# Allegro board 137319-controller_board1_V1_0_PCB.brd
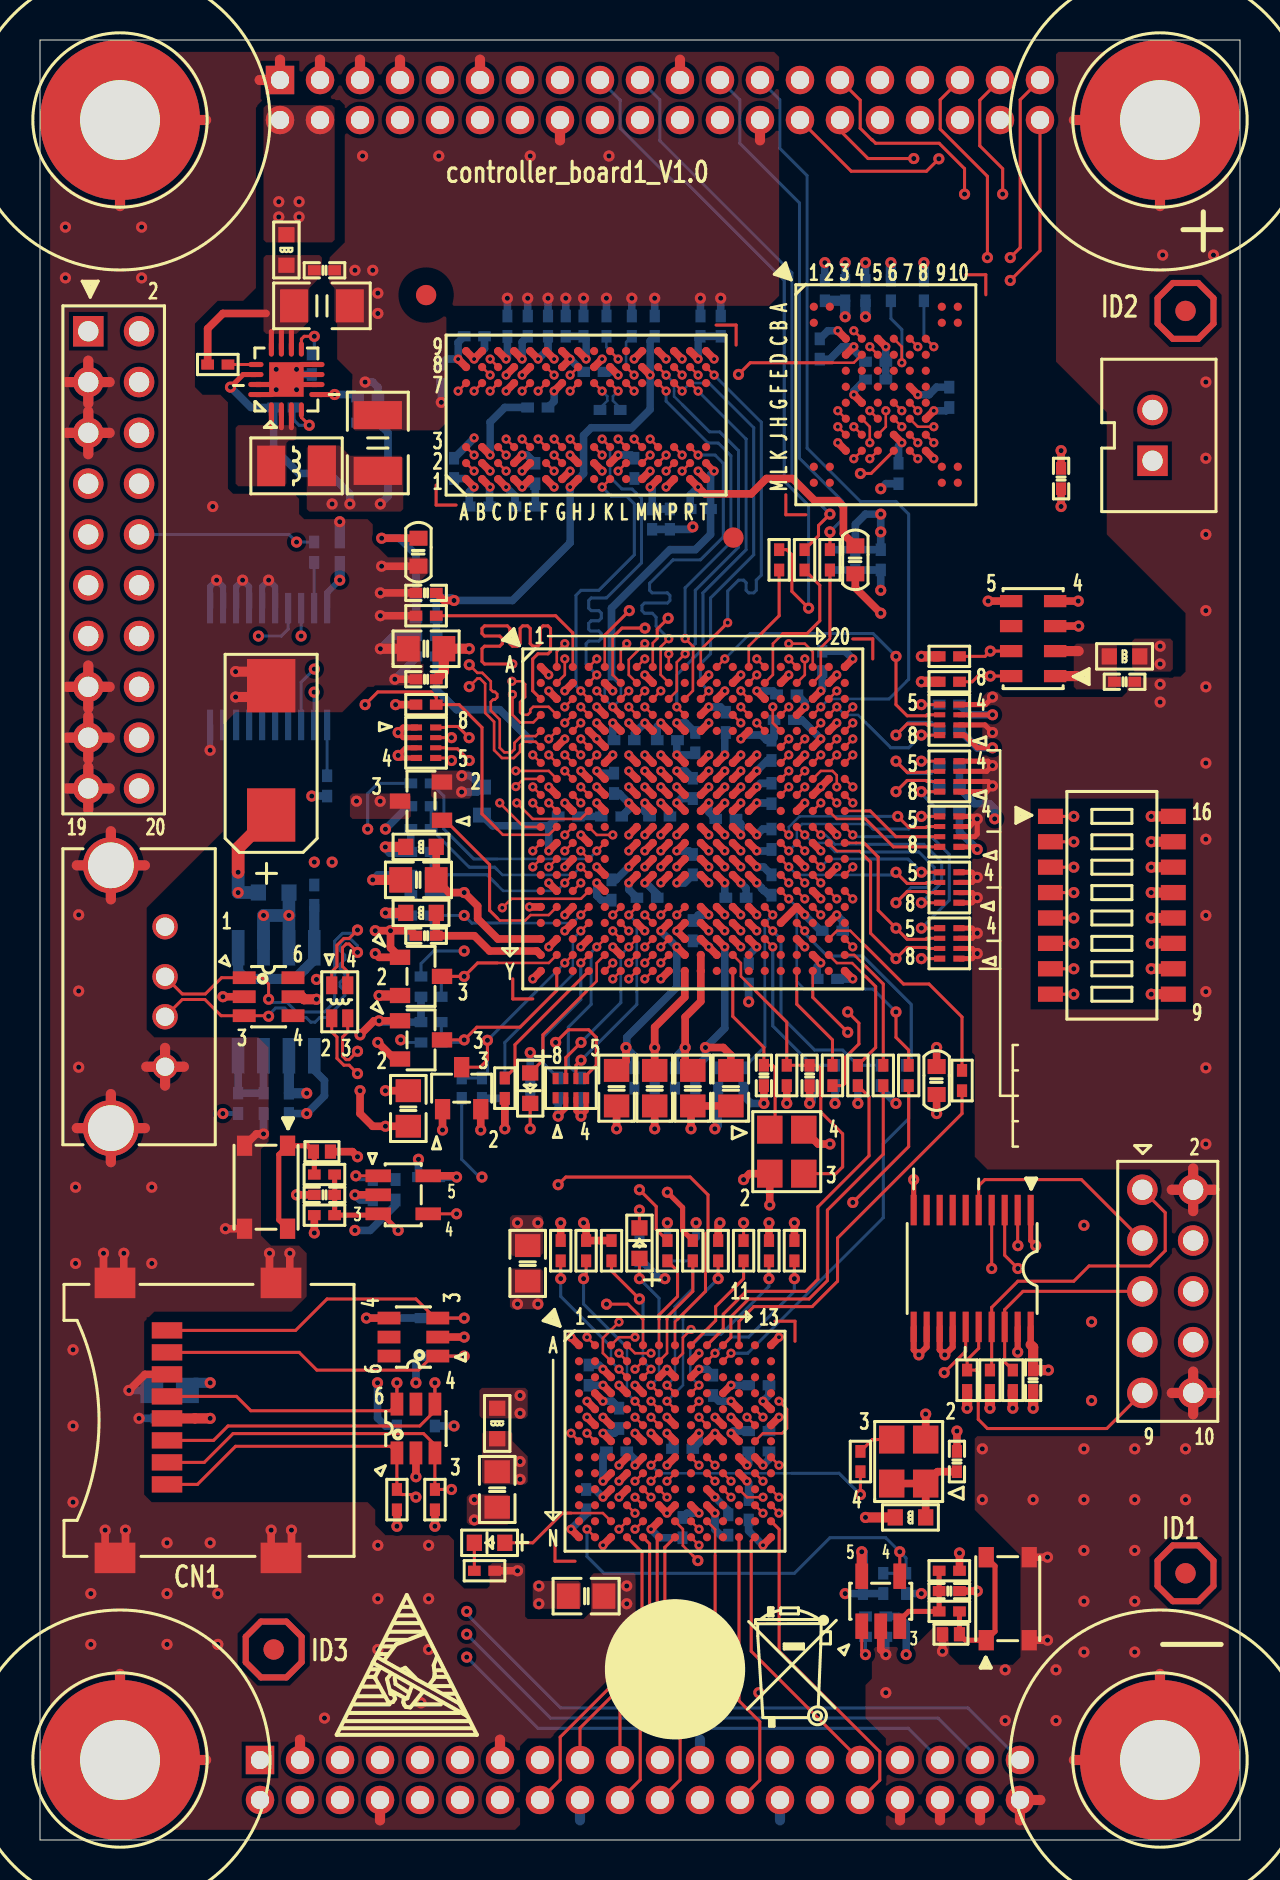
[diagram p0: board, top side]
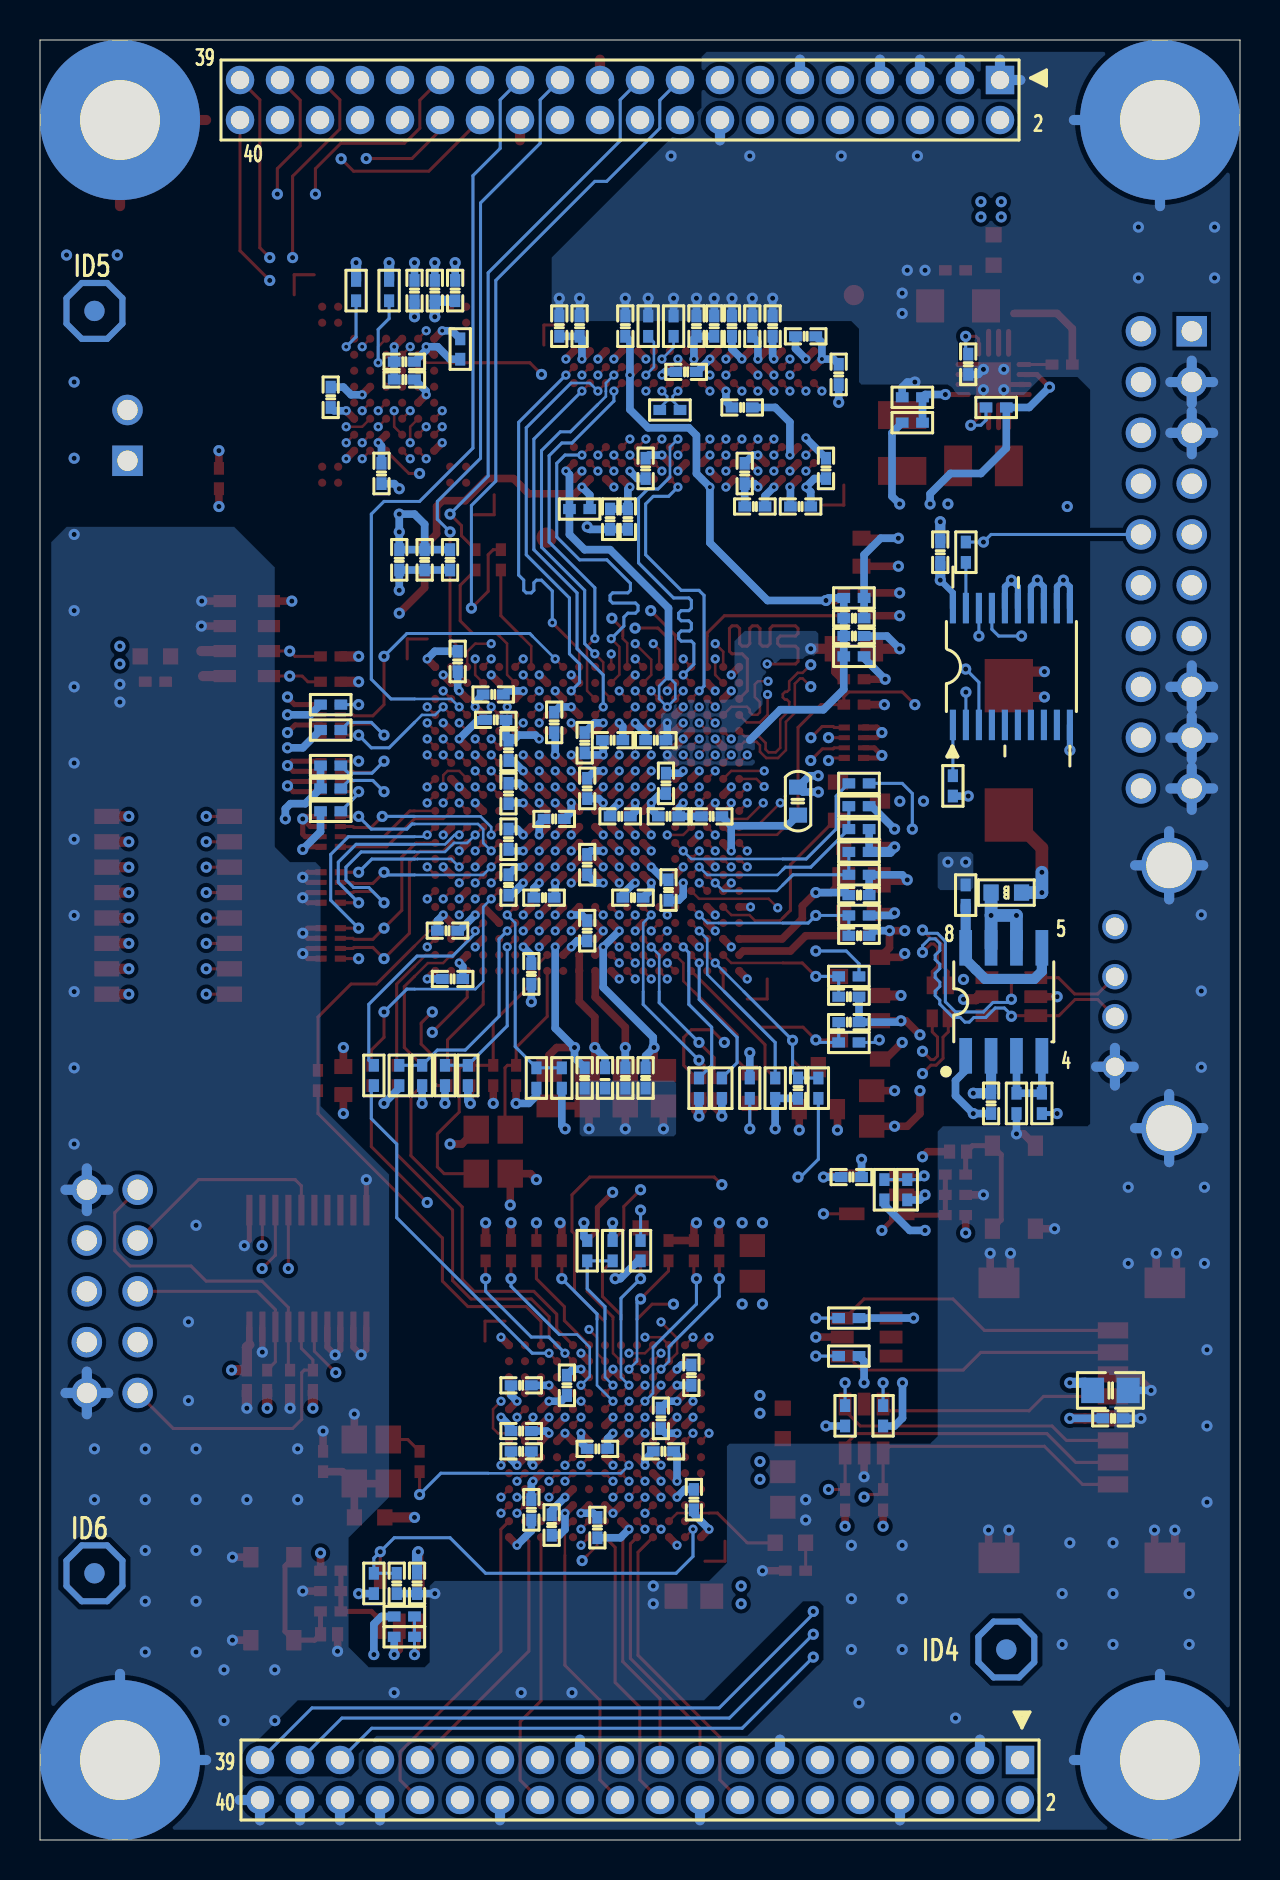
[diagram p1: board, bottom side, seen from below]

Outline 60 x 90 mm; copper layers: TOP, GND02, ART03, ART04, POWER05, BOTTOM. Coordinates in mm from the lower left corner of the outline.
Outline path: 0,90 0,0 60,0 60,90 0,90

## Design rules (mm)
net group DIFFPAIR0: nets USB_N USB_P
net group DIFFPAIR1: nets USB1_DN USB1_DP
net group DIFFPAIR2: nets USB0_DN USB0_DP

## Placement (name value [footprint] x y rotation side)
C1  0.1u  [C0402]  14.99 64.39 90 bottom
C2  0.1u  [C0402]  51.05 68.07 270 top
C3  0.1u  [C0402]  19.3 61.09 0 bottom
C4  0.1u  [C0402]  19.3 60.2 180 bottom
C5  0.1u  [C0402]  19.3 62.36 180 top
C6  0.1u  [C0402]  30.73 75.69 90 bottom
C7  1000p  [C0402]  23.37 75.69 90 bottom
C8  0.1u  [C0402]  21.97 66.67 0 bottom
C9  1000p  [C0402]  27.18 75.69 90 bottom
C10  0.1u  [C0402]  33.02 75.69 90 bottom
C11  1000p  [C0402]  26.29 75.69 90 bottom
C12  0.1u  [C0402]  34.04 75.69 90 bottom
C13  1000p  [C0402]  20.7 68.58 90 bottom
C14  0.1u  [C0402]  24.38 75.69 90 bottom
C15  1000p  [C0402]  24.26 66.67 0 bottom
C16  0.1u  [C0402]  21.72 75.18 0 bottom
C17  1000p  [C0402]  24.77 68.33 270 bottom
C18  0.1u  [C0402]  25.4 75.69 90 bottom
C19  1000p  [C0402]  30.61 66.04 270 bottom
C20  0.1u  [C0402]  27.69 73.41 180 bottom
C21  1000p  [C0402]  31.5 66.04 270 bottom
C22  0.1u  [C0402]  24.89 71.63 180 bottom
C23  1000p  [C0402]  20.07 73.28 270 bottom
C24  0.1u  [C0402]  29.72 68.58 270 bottom
C25  0.1u  [C0402]  41.78 73.91 0 bottom
C26  0.1u  [C0402]  42.93 68.33 270 bottom
C27  0.1u  [C0402]  45.47 72.14 90 bottom
C28  0.1u  [C0402]  41.78 73.03 0 bottom
C29  0.1u  [C0402]  19.56 42.16 180 bottom
C30  12p  [C0402]  38.48 38.23 270 top
C31  12p  [C0402]  36.2 38.23 270 top
C32  0.1u  [C0402]  22.1 37.59 270 bottom
C33  0.1u  [C0402]  19.56 40.89 180 bottom
C34  0.1u  [C0402]  19.05 45.21 180 bottom
C35  0.1u  [C0402]  54.23 57.91 0 top
C36  0.1u  [C0402]  19.43 33.15 180 bottom
C37  0.1u  [C0402]  14.22 32.26 180 top
C38  4.7u  [C0603]  40.77 64.01 270 top
C39  0.1u  [C0402]  28.57 51.18 0 bottom
C40  0.1u  [C0402]  28.7 52.83 270 bottom
C41  0.1u  [C0402]  34.29 55.88 270 bottom
C42  0.1u  [C0402]  26.42 51.18 180 bottom
C43  0.1u  [C0402]  31.37 54.99 0 bottom
C44  0.1u  [C0402]  29.21 54.99 0 bottom
C45  0.1u  [C0402]  19.3 58.04 180 top
C46  0.1u  [C0402]  32.64 45.47 270 bottom
C47  10u  [C0805]  19.3 59.56 180 top
C48  4.7u  [C0603]  22.1 51.94 270 bottom
C49  0.1u  [C0402]  36.58 47.75 90 bottom
C50  0.1u  [C0402]  34.29 51.05 180 bottom
C51  0.1u  [C0402]  36.58 50.04 90 bottom
C52  0.1u  [C0402]  36.58 52.32 90 bottom
C53  0.1u  [C0402]  28.57 47.5 270 bottom
C54  0.1u  [C0402]  36.58 54.48 90 bottom
C55  0.1u  [C0402]  34.8 47.12 0 bottom
C56  0.1u  [C0402]  32.64 52.58 270 bottom
C57  0.1u  [C0402]  30.99 51.18 0 bottom
C58  0.1u  [C0402]  32.64 48.77 90 bottom
C59  0.1u  [C0402]  32.77 54.86 270 bottom
C60  0.1u  [C0402]  30.35 47.12 180 bottom
C61  10u  [C0805]  34.54 37.59 270 top
C62  0.1u  [C0402]  32.77 38.1 270 bottom
C63  10u  [C0805]  18.41 36.58 270 top
C64  0.1u  [C0402]  39.37 43.05 0 bottom
C65  0.1u  [C0402]  40.77 64.01 90 bottom
C66  0.1u  [C0402]  39.12 58.93 90 bottom
C67  0.1u  [C0402]  35.43 43.31 270 bottom
C68  0.1u  [C0402]  39.62 45.47 0 bottom
C69  0.1u  [C0402]  39.5 64.01 90 bottom
C70  0.1u  [C0402]  40.26 77.47 90 bottom
C71  0.1u  [C0402]  37.21 56.01 180 bottom
C72  0.1u  [C0402]  37.34 57.28 0 bottom
C73  0.1u  [C0402]  41.27 77.47 90 bottom
C74  0.1u  [C0402]  39.24 77.47 90 bottom
C75  4.7u  [C0603]  44.83 37.97 270 top
C76  0.1u  [C0402]  42.04 64.01 90 bottom
C77  0.1u  [C0402]  31.75 38.1 270 bottom
C78  10u  [C0805]  32.64 37.59 270 top
C79  4.7u  [C0603]  18.92 64.39 270 top
C80  0.1u  [C0402]  29.72 38.1 270 bottom
C81  10u  [C0805]  28.83 37.59 270 top
C82  0.1u  [C0402]  30.73 38.1 270 bottom
C83  10u  [C0805]  30.73 37.59 270 top
C84  0.1u  [C0402]  19.3 45.21 180 top
C85  0.1u  [C0402]  19.05 47.24 180 bottom
C86  10u  [C0805]  18.92 48.01 180 top
C87  10u  [C0805]  6.48 22.48 180 bottom
C88  0.1u  [C0402]  6.35 21.08 0 bottom
C89  220u  [TC7343]  11.56 54.48 90 top
C90  0.1u  [C0402]  12.45 36.83 270 bottom
C91  0.1u  [C0402]  45.85 18.92 90 top
C92  0.1u  [C0402]  42.16 12.83 270 bottom
C93  0.1u  [C0402]  41.15 12.83 270 bottom
C94  0.1u  [C0402]  45.47 12.45 0 top
C95  10u  [C0805]  27.3 12.19 0 top
C96  1u  [C0402]  28.96 21.08 90 bottom
C97  0.1u  [C0402]  35.94 20.45 0 bottom
C98  0.1u  [C0402]  27.3 17.02 270 bottom
C99  0.1u  [C0402]  32.13 19.56 180 bottom
C100  0.1u  [C0402]  28.83 19.43 0 bottom
C101  10u  [C0805]  22.86 17.53 270 top
C102  1u  [C0402]  35.94 22.73 0 bottom
C103  0.1u  [C0402]  27.43 23.24 90 bottom
C104  0.1u  [C0402]  34.42 15.75 270 bottom
C105  10u  [C0805]  24.38 28.83 270 top
C106  1u  [C0402]  33.66 22.73 270 bottom
C107  0.1u  [C0402]  35.43 16.51 270 bottom
C108  0.1u  [C0402]  32.13 15.62 270 bottom
C109  0.1u  [C0402]  35.94 19.43 0 bottom
C110  0.1u  [C0402]  49.66 22.99 270 top
C111  22u  [C1210]  16.89 69.85 90 top
C112  47u  [C1206]  14.1 76.71 0 top
C113  0.1u  [C0402]  14.22 78.49 0 top
C114  160p  [C0402]  13.59 73.79 270 bottom
CN1  47219-2001  [SD12-47219-2001]  6.35 17.78 270 top
D1  APT1608SYCK  [D0603]  24.51 37.59 270 top
D2  BAT54S  [SOT23-3-095-3X1_4]  21.08 37.59 0 top
D3  BAT54S  [SOT23-3-095-3X1_4]  19.05 43.18 270 top
D4  BAT54S  [SOT23-3-095-3X1_4]  19.05 40.01 270 top
D5  Rclamp0531t  [SLP1006P2T]  14.1 34.42 180 top
D6  APT1608SYCK  [D0603]  22.48 14.86 180 top
D7  Rclamp0531t  [SLP1006P2T]  45.55 10.29 0 top
D8  APT1608SYCK  [D0603]  29.97 29.84 90 top
FB1  BLM18PG121SH1D  [FB0603]  54.23 59.18 0 top
FB2  BLM18PG121SH1D  [FB0603]  19.05 49.66 180 top
FB3  BLM18PG121SH1D  [FB0603]  19.05 46.35 180 top
FB4  BLM18PG121SH1D  [FB0603]  11.68 47.37 0 bottom
FB5  BLM18PG121SH1D  [FB0603]  43.52 16.13 180 top
FB6  BLM18PG121SH1D  [FB0603]  22.86 20.83 270 top
FB7  BLM18PG121SH1D  [FB0603]  12.32 79.5 270 top
H1  MH-7R4D3R2  [HOLE315-157]  4 4 0 top
H2  MH-7R4D3R2  [HOLE315-157]  56 4 0 top
H3  MH-7R4D3R2  [HOLE315-157]  56 86 0 top
H4  MH-7R4D3R2  [HOLE315-157]  4 86 0 top
J1  877584017  [HD40-2_0]  31 87 0 bottom
J2  877584017  [HD40-2_0]  30 3 0 bottom
J3  90131-1090  [HD20-2_54]  3.68 64.01 270 top
J4  0901311081  [SIP2-2_54]  55.63 70.23 270 top
J5  1734366-3  [USB4-AF]  4.95 42.16 270 top
J6  0901311085  [HD10-2_54]  56.39 27.43 270 top
L1  ACM2012H  [L4-0805]  14.99 41.91 270 top
L2  2.2uH  [L1008]  12.83 68.71 0 top
NOREF  -  []  281.94 115.57 0 top
NOREF#2  -  []  32.26 8.76 0 top
NOREF#3  -  []  459.86 195.16 0 top
NOREF#4  -  []  140.97 -11.43 0 top
NOREF#5  -  []  0 90 0 top
NOREF#6  -  []  459.86 210.4 0 top
NOREF#7  -  []  459.86 202.78 0 top
NOREF#8  -  []  40.13 8.76 0 top
NOREF#9  -  []  434.46 210.4 0 top
NOREF#10  -  [unnamed#2]  57.28 13.34 0 top
NOREF#11  -  []  257.81 180.34 0 top
NOREF#12  -  [unnamed#2]  11.68 9.53 0 top
NOREF#13  -  [unnamed#2]  57.28 76.45 0 top
NOREF#14  -  []  434.46 202.78 0 top
NOREF#15  -  []  434.46 195.16 0 top
NOREF#16  -  []  17.65 8.26 0 top
NOREF#17  -  []  250.32 7.75 0 top
NOREF#18  -  []  -19.05 -43.18 0 top
NOREF#19  -  []  250.32 63.75 0 top
NOREF#20  -  []  0 0 90 top
NOREF#21  -  [unnamed#2]  11.68 9.53 180 bottom
NOREF#22  -  [unnamed#2]  57.28 13.34 180 bottom
NOREF#23  -  [unnamed#2]  57.28 76.45 180 bottom
Q1  PBSS4021NT  [SOT23-3-095-3X1_4]  19.05 51.94 90 top
R1  0  [R0402]  45.47 56.77 0 bottom
R2  0  [R0402]  45.47 55.5 0 bottom
R3  0  [R0402]  45.47 53.72 0 bottom
R4  0  [R0402]  45.47 52.58 0 bottom
R5  0  [R0402]  45.47 51.44 0 bottom
R6  0  [R0402]  14.36 52.7 270 bottom
R7  0  [R0402]  13.71 64.39 90 bottom
R8  240  [R0402]  19.3 62.1 0 bottom
R9  240  [R0402]  19.3 59.18 180 bottom
R10  100  [R0402]  28.51 71.5 0 bottom
R11  10K  [R0402]  33.02 66.55 0 bottom
R12  240  [R0402]  19.3 61.21 180 top
R13  240  [R0402]  29.59 75.69 90 bottom
R14  10K  [R0402]  28.32 75.69 90 bottom
R15  4.7K  [R0402]  38.99 74.55 90 bottom
R16  4.7K  [R0402]  42.55 77.47 270 bottom
R17  4.7K  [R0402]  44.2 77.47 270 bottom
R18  33  [R0402]  42.16 38.23 270 top
R19  33  [R0402]  43.43 38.23 90 top
R20  33  [R0402]  39.62 38.23 270 top
R21  33  [R0402]  40.89 38.23 270 top
R22  33  [R0402]  46.1 37.97 270 top
R23  33  [R0402]  43.31 38.23 270 bottom
R24  33  [R0402]  39.5 64.01 270 top
R25  33  [R0402]  38.23 64.01 270 top
R26  33  [R0402]  36.96 64.01 270 top
R27  4.7K  [R0402]  19.3 56.77 180 top
R28  33  [R0402]  19.05 52.83 0 bottom
R29  4.7K  [R0402]  33.91 38.1 90 bottom
R30  4.7K  [R0402]  35.18 38.1 270 bottom
R31  4.7K  [R0402]  42.04 38.23 90 bottom
R32  4.7K  [R0402]  40.89 38.23 270 bottom
R33  4.7K  [R0402]  19.05 50.55 0 bottom
R34  4.7K  [R0402]  19.05 51.69 180 bottom
R35  4.7K  [R0402]  19.05 49.4 0 bottom
R36  4.7K  [R0402]  19.05 48.26 180 bottom
R37  1K  [R0402]  24.51 37.59 270 bottom
R38  1K  [R0402]  19.56 39.88 180 bottom
R39  1K  [R0402]  19.56 43.18 180 bottom
R40  1K  [R0402]  21.08 37.59 270 bottom
R42  2.2M  [R0402]  37.34 38.23 270 top
R46  10K  [R0402]  19.05 46.23 0 bottom
R47  10K  [R0402]  14.22 31.24 180 top
R48  10K  [R0402]  45.47 59.18 180 top
R49  10K  [R0402]  45.47 57.91 180 top
R50  10K  [R0402]  17.78 32.51 270 bottom
R51  0  [R0402]  14.22 33.27 180 top
R52  10K  [R0402]  16.64 32.51 270 bottom
R53  10K  [R0402]  17.85 17.02 90 top
R54  10K  [R0402]  19.75 17.02 90 top
R55  10K  [R0402]  19.75 21.21 90 bottom
R56  10K  [R0402]  17.85 21.21 90 bottom
R57  10K  [R0402]  19.56 24.2 0 bottom
R58  10K  [R0402]  19.56 26.1 0 bottom
R59  4.7K  [R0402]  38.61 38.23 270 bottom
R60  4.7K  [R0402]  39.75 38.23 270 bottom
R61  10K  [R0402]  13.72 47.24 90 bottom
R62  0  [R0402]  9.91 36.83 270 bottom
R63  4.7K  [R0402]  11.18 36.83 90 bottom
R64  33  [R0402]  35.18 29.46 270 top
R65  33  [R0402]  31.37 29.46 270 top
R66  0  [R0402]  32.64 29.46 270 top
R67  1K  [R0402]  22.23 13.46 0 top
R68  33  [R0402]  41.02 18.92 90 top
R69  10K  [R0402]  43.31 12.83 90 bottom
R70  10K  [R0402]  45.47 13.46 0 top
R71  10K  [R0402]  41.78 11.18 0 bottom
R72  0  [R0402]  45.47 11.43 0 top
R73  10K  [R0402]  41.78 10.16 0 bottom
R74  10K  [R0402]  32.64 29.46 270 bottom
R75  10K  [R0402]  31.37 29.46 90 bottom
R76  10K  [R0402]  37.72 29.46 270 top
R77  10K  [R0402]  36.45 29.46 270 top
R78  1K  [R0402]  29.97 29.46 90 bottom
R79  10K  [R0402]  26.04 29.46 270 top
R80  10K  [R0402]  28.57 29.46 270 top
R81  10K  [R0402]  33.91 29.46 270 top
R82  10K  [R0402]  27.3 29.46 270 top
R83  1K  [R0402]  47.5 22.99 90 top
R84  10K  [R0402]  48.64 22.99 90 top
R85  10K  [R0402]  46.35 22.99 90 top
R86  0  [R0402]  8.89 73.78 0 top
R87  4.7K  [R0402]  12.19 71.63 180 bottom
R88  130k  [R0402]  16.38 70.87 180 bottom
R89  150k  [R0402]  16.38 72.14 0 bottom
R90  1K  [R0402]  23.24 37.59 270 top
R91  1K  [R0402]  23.24 37.59 270 bottom
R92  1K  [R0402]  25.91 37.59 270 bottom
R93  1K  [R0402]  27.05 37.59 270 bottom
RA1  10k  [RN8-0402]  45.47 47.62 90 top
RA2  10k  [RN8-0402]  45.47 44.83 90 top
RA3  10k  [RN8-0402]  45.47 50.42 90 top
RA4  10k  [RN8-0402]  45.47 56.01 90 top
RA5  10k  [RN8-0402]  45.47 53.18 90 top
RA6  10k  [RN8-0402]  26.54 37.59 0 top
RA7  10k  [RN8-0402]  19.3 54.86 270 top
S1  97C08SRT  [SW16-1_27MM-4_55]  53.59 46.74 270 top
SW1  PTS810 SJM 250 SMTR LFS  [SW4-0403]  11.3 32.64 270 top
SW2  PTS810 SJM 250 SMTR LFS  [SW4-0403]  48.39 12.06 90 top
U2  MVF61NS151CMK50  [BGA364_0P8_17X17]  32.64 51.05 270 top
U3  MT41J64M16JT-15E IT  [BGA96-0_8-1609]  27.3 71.25 0 top
U4  MT29F2G08ABAEAH4-IT  [BGA63-0_8-1210]  42.29 72.26 270 top
U5  MS560702BA03-50  [DFN8-1_25-5_0X3_0-H1_0]  49.66 60.07 90 top
U7  RCLAMP0504S.TCT  [SOT23-6-095-2_9X1_6]  18.8 20.57 0 top
U8  RCLAMP0504S.TCT  [SOT23-6-095-2_9X1_6]  18.67 25.15 90 top
U9  TPS2042BDR  [SOP8-50-157]  11.81 41.91 180 bottom
U10  RCLAMP0504S.TCT  [SOT23-6-095-2_9X1_6]  11.43 42.16 270 top
U11  10M08SCU169I7G  [BGA169-0_8-1111]  31.75 19.94 270 top
U14  TPS62140ARGTR  [QFN16-050-0303LH]  12.32 73.03 0 top
U15  SN74LVCR2245APWR  [SOP20-26-173]  11.43 58.67 180 bottom
U16  SN74LVCR2245APWR  [SOP20-26-173]  46.61 28.57 180 top
U17  TPS3838K  [SOT23-5-095-2_9X1_6]  42.04 11.94 0 top
U18  TPS3838K  [SOT23-5-095-2_9X1_6]  18.16 32.26 270 top
X1  8MHz  [X4-3225]  43.43 18.92 90 top
Y1  24MHz  [X4-3225]  37.34 34.42 270 top

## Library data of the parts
C1-C88 C90-C114 = CAP
C89 = CAP_POL
CN1 = MICRO_SD_CARD
D1 D6 D8 = LED
D2-D4 = DIODE_SCHOTTKY_2
D5 D7 = DIODE-BI
FB1-FB7 = FB
H1-H4 = HOLE
J1 J2 = HEADER 20X2
J3 = HEADER 10X2
J4 = JUMPER
J5 = USB-A
J6 = HEADER 5X2
L1 = INDUCTOR-COM
L2 = INDUCTOR
Q1 = TRANSISTOR_NPN
R1-R9 R11-R13 R15-R40 R42 R46-R93 = RES
R10 = RES: signal model: RES_R0402_DISCRETE_100_100
R14 = RES: signal model: RES_R0402_DISCRETE_10K_10K
RA1-RA7 = RP4
S1 = SWITCH-8
SW1 SW2 = SWITCH-PUSH
U2 = MVF61NS151CMK50
U3 = DDR3SDRAM16
U4 = NAND16-BGA63
U5 = MS560702BA03
U7 U8 U10 = TVS_ARRAY4_P
U9 = TPS2042
U11 = 10M08SCU169
U14 = TPS62140
U15 U16 = SN74LVCR2245
U17 U18 = TPS3838K
X1 = CLOCK
Y1 = CRYSTAL-4

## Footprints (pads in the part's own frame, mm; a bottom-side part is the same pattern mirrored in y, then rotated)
BGA63-0_8-1210
  round 0.406 smd: A1(-4.4,-3.6) A2(-4.4,-2.8) A9(-4.4,2.8) A10(-4.4,3.6) B1(-3.6,-3.6) B9(-3.6,2.8) B10(-3.6,3.6) C3(-2.8,-2) C4(-2.8,-1.2) C5(-2.8,-0.4) C6(-2.8,0.4) C7(-2.8,1.2) C8(-2.8,2) D3(-2,-2) D4(-2,-1.2) D5(-2,-0.4) D6(-2,0.4) D7(-2,1.2) D8(-2,2) E3(-1.2,-2) E4(-1.2,-1.2) E5(-1.2,-0.4) E6(-1.2,0.4) E7(-1.2,1.2) E8(-1.2,2) F3(-0.4,-2) F4(-0.4,-1.2) F5(-0.4,-0.4) F6(-0.4,0.4) F7(-0.4,1.2) F8(-0.4,2) G3(0.4,-2) G4(0.4,-1.2) G5(0.4,-0.4) G6(0.4,0.4) G7(0.4,1.2) G8(0.4,2) H3(1.2,-2) H4(1.2,-1.2) H5(1.2,-0.4) H6(1.2,0.4) H7(1.2,1.2) H8(1.2,2) J3(2,-2) J4(2,-1.2) J5(2,-0.4) J6(2,0.4) J7(2,1.2) J8(2,2) K3(2.8,-2) K4(2.8,-1.2) K5(2.8,-0.4) K6(2.8,0.4) K7(2.8,1.2) K8(2.8,2) L1(3.6,-3.6) L2(3.6,-2.8) L9(3.6,2.8) L10(3.6,3.6) M1(4.4,-3.6) M2(4.4,-2.8) M9(4.4,2.8) M10(4.4,3.6)
BGA96-0_8-1609
  round 1.016 smd: (-8,6) (7.365,-6.127)
  round 0.406 smd: A1(-6,-3.2) A2(-6,-2.4) A3(-6,-1.6) A7(-6,1.6) A8(-6,2.4) A9(-6,3.2) B1(-5.2,-3.2) B2(-5.2,-2.4) B3(-5.2,-1.6) B7(-5.2,1.6) B8(-5.2,2.4) B9(-5.2,3.2) C1(-4.4,-3.2) C2(-4.4,-2.4) C3(-4.4,-1.6) C7(-4.4,1.6) C8(-4.4,2.4) C9(-4.4,3.2) D1(-3.6,-3.2) D2(-3.6,-2.4) D3(-3.6,-1.6) D7(-3.6,1.6) D8(-3.6,2.4) D9(-3.6,3.2) E1(-2.8,-3.2) E2(-2.8,-2.4) E3(-2.8,-1.6) E7(-2.8,1.6) E8(-2.8,2.4) E9(-2.8,3.2) F1(-2,-3.2) F2(-2,-2.4) F3(-2,-1.6) F7(-2,1.6) F8(-2,2.4) F9(-2,3.2) G1(-1.2,-3.2) G2(-1.2,-2.4) G3(-1.2,-1.6) G7(-1.2,1.6) G8(-1.2,2.4) G9(-1.2,3.2) H1(-0.4,-3.2) H2(-0.4,-2.4) H3(-0.4,-1.6) H7(-0.4,1.6) H8(-0.4,2.4) H9(-0.4,3.2) J1(0.4,-3.2) J2(0.4,-2.4) J3(0.4,-1.6) J7(0.4,1.6) J8(0.4,2.4) J9(0.4,3.2) K1(1.2,-3.2) K2(1.2,-2.4) K3(1.2,-1.6) K7(1.2,1.6) K8(1.2,2.4) K9(1.2,3.2) L1(2,-3.2) L2(2,-2.4) L3(2,-1.6) L7(2,1.6) L8(2,2.4) L9(2,3.2) M1(2.8,-3.2) M2(2.8,-2.4) M3(2.8,-1.6) M7(2.8,1.6) M8(2.8,2.4) M9(2.8,3.2) N1(3.6,-3.2) N2(3.6,-2.4) N3(3.6,-1.6) N7(3.6,1.6) N8(3.6,2.4) N9(3.6,3.2) P1(4.4,-3.2) P2(4.4,-2.4) P3(4.4,-1.6) P7(4.4,1.6) P8(4.4,2.4) P9(4.4,3.2) R1(5.2,-3.2) R2(5.2,-2.4) R3(5.2,-1.6) R7(5.2,1.6) R8(5.2,2.4) R9(5.2,3.2) T1(6,-3.2) T2(6,-2.4) T3(6,-1.6) T7(6,1.6) T8(6,2.4) T9(6,3.2)
BGA169-0_8-1111
  round 0.406 smd: A1(-4.8,-4.8) A2(-4.8,-4) A3(-4.8,-3.2) A4(-4.8,-2.4) A5(-4.8,-1.6) A6(-4.8,-0.8) A7(-4.8,0) A8(-4.8,0.8) A9(-4.8,1.6) A10(-4.8,2.4) A11(-4.8,3.2) A12(-4.8,4) A13(-4.8,4.8) B1(-4,-4.8) B2(-4,-4) B3(-4,-3.2) B4(-4,-2.4) B5(-4,-1.6) B6(-4,-0.8) B7(-4,0) B8(-4,0.8) B9(-4,1.6) B10(-4,2.4) B11(-4,3.2) B12(-4,4) B13(-4,4.8) C1(-3.2,-4.8) C2(-3.2,-4) C3(-3.2,-3.2) C4(-3.2,-2.4) C5(-3.2,-1.6) C6(-3.2,-0.8) C7(-3.2,0) C8(-3.2,0.8) C9(-3.2,1.6) C10(-3.2,2.4) C11(-3.2,3.2) C12(-3.2,4) C13(-3.2,4.8) D1(-2.4,-4.8) D2(-2.4,-4) D3(-2.4,-3.2) D4(-2.4,-2.4) D5(-2.4,-1.6) D6(-2.4,-0.8) D7(-2.4,0) D8(-2.4,0.8) D9(-2.4,1.6) D10(-2.4,2.4) D11(-2.4,3.2) D12(-2.4,4) D13(-2.4,4.8) E1(-1.6,-4.8) E2(-1.6,-4) E3(-1.6,-3.2) E4(-1.6,-2.4) E5(-1.6,-1.6) E6(-1.6,-0.8) E7(-1.6,0) E8(-1.6,0.8) E9(-1.6,1.6) E10(-1.6,2.4) E11(-1.6,3.2) E12(-1.6,4) E13(-1.6,4.8) F1(-0.8,-4.8) F2(-0.8,-4) F3(-0.8,-3.2) F4(-0.8,-2.4) F5(-0.8,-1.6) F6(-0.8,-0.8) F7(-0.8,0) F8(-0.8,0.8) F9(-0.8,1.6) F10(-0.8,2.4) F11(-0.8,3.2) F12(-0.8,4) F13(-0.8,4.8) G1(0,-4.8) G2(0,-4) G3(0,-3.2) G4(0,-2.4) G5(0,-1.6) G6(0,-0.8) G7(0,0) G8(0,0.8) G9(0,1.6) G10(0,2.4) G11(0,3.2) G12(0,4) G13(0,4.8) H1(0.8,-4.8) H2(0.8,-4) H3(0.8,-3.2) H4(0.8,-2.4) H5(0.8,-1.6) H6(0.8,-0.8) H7(0.8,0) H8(0.8,0.8) H9(0.8,1.6) H10(0.8,2.4) H11(0.8,3.2) H12(0.8,4) H13(0.8,4.8) J1(1.6,-4.8) J2(1.6,-4) J3(1.6,-3.2) J4(1.6,-2.4) J5(1.6,-1.6) J6(1.6,-0.8) J7(1.6,0) J8(1.6,0.8) J9(1.6,1.6) J10(1.6,2.4) J11(1.6,3.2) J12(1.6,4) J13(1.6,4.8) K1(2.4,-4.8) K2(2.4,-4) K3(2.4,-3.2) K4(2.4,-2.4) K5(2.4,-1.6) K6(2.4,-0.8) K7(2.4,0) K8(2.4,0.8) K9(2.4,1.6) K10(2.4,2.4) K11(2.4,3.2) K12(2.4,4) K13(2.4,4.8) L1(3.2,-4.8) L2(3.2,-4) L3(3.2,-3.2) L4(3.2,-2.4) L5(3.2,-1.6) L6(3.2,-0.8) L7(3.2,0) L8(3.2,0.8) L9(3.2,1.6) L10(3.2,2.4) L11(3.2,3.2) L12(3.2,4) L13(3.2,4.8) M1(4,-4.8) M2(4,-4) M3(4,-3.2) M4(4,-2.4) M5(4,-1.6) M6(4,-0.8) M7(4,0) M8(4,0.8) M9(4,1.6) M10(4,2.4) M11(4,3.2) M12(4,4) M13(4,4.8) N1(4.8,-4.8) N2(4.8,-4) N3(4.8,-3.2) N4(4.8,-2.4) N5(4.8,-1.6) N6(4.8,-0.8) N7(4.8,0) N8(4.8,0.8) N9(4.8,1.6) N10(4.8,2.4) N11(4.8,3.2) N12(4.8,4) N13(4.8,4.8)
BGA364_0P8_17X17
  round 0.406 smd: A1(-7.6,-7.6) A2(-7.6,-6.8) A3(-7.6,-6) A4(-7.6,-5.2) A5(-7.6,-4.4) A6(-7.6,-3.6) A7(-7.6,-2.8) A8(-7.6,-2) A9(-7.6,-1.2) A10(-7.6,-0.4) A11(-7.6,0.4) A12(-7.6,1.2) A13(-7.6,2) A14(-7.6,2.8) A15(-7.6,3.6) A16(-7.6,4.4) A17(-7.6,5.2) A18(-7.6,6) A19(-7.6,6.8) A20(-7.6,7.6) B1(-6.8,-7.6) B2(-6.8,-6.8) B3(-6.8,-6) B4(-6.8,-5.2) B5(-6.8,-4.4) B6(-6.8,-3.6) B7(-6.8,-2.8) B8(-6.8,-2) B9(-6.8,-1.2) B10(-6.8,-0.4) B11(-6.8,0.4) B12(-6.8,1.2) B13(-6.8,2) B14(-6.8,2.8) B15(-6.8,3.6) B16(-6.8,4.4) B17(-6.8,5.2) B18(-6.8,6) B19(-6.8,6.8) B20(-6.8,7.6) C1(-6,-7.6) C2(-6,-6.8) C3(-6,-6) C4(-6,-5.2) C5(-6,-4.4) C6(-6,-3.6) C7(-6,-2.8) C8(-6,-2) C9(-6,-1.2) C10(-6,-0.4) C11(-6,0.4) C12(-6,1.2) C13(-6,2) C14(-6,2.8) C15(-6,3.6) C16(-6,4.4) C17(-6,5.2) C18(-6,6) C19(-6,6.8) C20(-6,7.6) D1(-5.2,-7.6) D2(-5.2,-6.8) D3(-5.2,-6) D4(-5.2,-5.2) D5(-5.2,-4.4) D6(-5.2,-3.6) D7(-5.2,-2.8) D8(-5.2,-2) D9(-5.2,-1.2) D10(-5.2,-0.4) D11(-5.2,0.4) D12(-5.2,1.2) D13(-5.2,2) D14(-5.2,2.8) D15(-5.2,3.6) D16(-5.2,4.4) D17(-5.2,5.2) D18(-5.2,6) D19(-5.2,6.8) D20(-5.2,7.6) E1(-4.4,-7.6) E2(-4.4,-6.8) E3(-4.4,-6) E4(-4.4,-5.2) E5(-4.4,-4.4) E6(-4.4,-3.6) E7(-4.4,-2.8) E8(-4.4,-2) E9(-4.4,-1.2) E10(-4.4,-0.4) E11(-4.4,0.4) E12(-4.4,1.2) E13(-4.4,2) E14(-4.4,2.8) E15(-4.4,3.6) E16(-4.4,4.4) E17(-4.4,5.2) E18(-4.4,6) E19(-4.4,6.8) E20(-4.4,7.6) F1(-3.6,-7.6) F2(-3.6,-6.8) F3(-3.6,-6) F4(-3.6,-5.2) F5(-3.6,-4.4) F16(-3.6,4.4) F17(-3.6,5.2) F18(-3.6,6) F19(-3.6,6.8) F20(-3.6,7.6) G1(-2.8,-7.6) G2(-2.8,-6.8) G3(-2.8,-6) G4(-2.8,-5.2) G5(-2.8,-4.4) G7(-2.8,-2.8) G8(-2.8,-2) G9(-2.8,-1.2) G10(-2.8,-0.4) G11(-2.8,0.4) G12(-2.8,1.2) G13(-2.8,2) G14(-2.8,2.8) G16(-2.8,4.4) G17(-2.8,5.2) G18(-2.8,6) G19(-2.8,6.8) G20(-2.8,7.6) H1(-2,-7.6) H2(-2,-6.8) H3(-2,-6) H4(-2,-5.2) H5(-2,-4.4) H7(-2,-2.8) H8(-2,-2) H9(-2,-1.2) H10(-2,-0.4) H11(-2,0.4) H12(-2,1.2) H13(-2,2) H14(-2,2.8) H16(-2,4.4) H17(-2,5.2) H18(-2,6) H19(-2,6.8) H20(-2,7.6) J1(-1.2,-7.6) J2(-1.2,-6.8) J3(-1.2,-6) J4(-1.2,-5.2) J5(-1.2,-4.4) J7(-1.2,-2.8) J8(-1.2,-2) J9(-1.2,-1.2) J10(-1.2,-0.4) J11(-1.2,0.4) J12(-1.2,1.2) J13(-1.2,2) J14(-1.2,2.8) J16(-1.2,4.4) J17(-1.2,5.2) J18(-1.2,6) J19(-1.2,6.8) J20(-1.2,7.6) K1(-0.4,-7.6) K2(-0.4,-6.8) K3(-0.4,-6) K4(-0.4,-5.2) K5(-0.4,-4.4) K7(-0.4,-2.8) K8(-0.4,-2) K9(-0.4,-1.2) K10(-0.4,-0.4) K11(-0.4,0.4) K12(-0.4,1.2) K13(-0.4,2) K14(-0.4,2.8) K16(-0.4,4.4) K17(-0.4,5.2) K18(-0.4,6) K19(-0.4,6.8) K20(-0.4,7.6) L1(0.4,-7.6) L2(0.4,-6.8) L3(0.4,-6) L4(0.4,-5.2) L5(0.4,-4.4) L7(0.4,-2.8) L8(0.4,-2) L9(0.4,-1.2) L10(0.4,-0.4) L11(0.4,0.4) L12(0.4,1.2) L13(0.4,2) L14(0.4,2.8) L16(0.4,4.4) L17(0.4,5.2) L18(0.4,6) L19(0.4,6.8) L20(0.4,7.6) M1(1.2,-7.6) M2(1.2,-6.8) M3(1.2,-6) M4(1.2,-5.2) M5(1.2,-4.4) M7(1.2,-2.8) M8(1.2,-2) M9(1.2,-1.2) M10(1.2,-0.4) M11(1.2,0.4) M12(1.2,1.2) M13(1.2,2) M14(1.2,2.8) M16(1.2,4.4) M17(1.2,5.2) M18(1.2,6) M19(1.2,6.8) M20(1.2,7.6) N1(2,-7.6) N2(2,-6.8) N3(2,-6) N4(2,-5.2) N5(2,-4.4) N7(2,-2.8) N8(2,-2) N9(2,-1.2) N10(2,-0.4) N11(2,0.4) N12(2,1.2) N13(2,2) N14(2,2.8) N16(2,4.4) N17(2,5.2) N18(2,6) N19(2,6.8) N20(2,7.6) P1(2.8,-7.6) P2(2.8,-6.8) P3(2.8,-6) P4(2.8,-5.2) P5(2.8,-4.4) P7(2.8,-2.8) P8(2.8,-2) P9(2.8,-1.2) P10(2.8,-0.4) P11(2.8,0.4) P12(2.8,1.2) P13(2.8,2) P14(2.8,2.8) P16(2.8,4.4) P17(2.8,5.2) P18(2.8,6) P19(2.8,6.8) P20(2.8,7.6) R1(3.6,-7.6) R2(3.6,-6.8) R3(3.6,-6) R4(3.6,-5.2) R5(3.6,-4.4) R16(3.6,4.4) R17(3.6,5.2) R18(3.6,6) R19(3.6,6.8) R20(3.6,7.6) T1(4.4,-7.6) T2(4.4,-6.8) T3(4.4,-6) T4(4.4,-5.2) T5(4.4,-4.4) T6(4.4,-3.6) T7(4.4,-2.8) T8(4.4,-2) T9(4.4,-1.2) T10(4.4,-0.4) T11(4.4,0.4) T12(4.4,1.2) T13(4.4,2) T14(4.4,2.8) T15(4.4,3.6) T16(4.4,4.4) T17(4.4,5.2) T18(4.4,6) T19(4.4,6.8) T20(4.4,7.6) U1(5.2,-7.6) U2(5.2,-6.8) U3(5.2,-6) U4(5.2,-5.2) U5(5.2,-4.4) U6(5.2,-3.6) U7(5.2,-2.8) U8(5.2,-2) U9(5.2,-1.2) U10(5.2,-0.4) U11(5.2,0.4) U12(5.2,1.2) U13(5.2,2) U14(5.2,2.8) U15(5.2,3.6) U16(5.2,4.4) U17(5.2,5.2) U18(5.2,6) U19(5.2,6.8) U20(5.2,7.6) V1(6,-7.6) V2(6,-6.8) V3(6,-6) V4(6,-5.2) V5(6,-4.4) V6(6,-3.6) V7(6,-2.8) V8(6,-2) V9(6,-1.2) V10(6,-0.4) V11(6,0.4) V12(6,1.2) V13(6,2) V14(6,2.8) V15(6,3.6) V16(6,4.4) V17(6,5.2) V18(6,6) V19(6,6.8) V20(6,7.6) W1(6.8,-7.6) W2(6.8,-6.8) W3(6.8,-6) W4(6.8,-5.2) W5(6.8,-4.4) W6(6.8,-3.6) W7(6.8,-2.8) W8(6.8,-2) W9(6.8,-1.2) W10(6.8,-0.4) W11(6.8,0.4) W12(6.8,1.2) W13(6.8,2) W14(6.8,2.8) W15(6.8,3.6) W16(6.8,4.4) W17(6.8,5.2) W18(6.8,6) W19(6.8,6.8) W20(6.8,7.6) Y1(7.6,-7.6) Y2(7.6,-6.8) Y3(7.6,-6) Y4(7.6,-5.2) Y5(7.6,-4.4) Y6(7.6,-3.6) Y7(7.6,-2.8) Y8(7.6,-2) Y9(7.6,-1.2) Y10(7.6,-0.4) Y11(7.6,0.4) Y12(7.6,1.2) Y13(7.6,2) Y14(7.6,2.8) Y15(7.6,3.6) Y16(7.6,4.4) Y17(7.6,5.2) Y18(7.6,6) Y19(7.6,6.8) Y20(7.6,7.6)
C0402
  rect 0.635x0.508 smd: 1(-0.508,0) 2(0.508,0)
C0603
  rect 0.75x0.9 smd: 1(-0.7,0) 2(0.7,0)
C0805
  rect 1.143x1.27 smd: 1(-0.889,0) 2(0.889,0)
C1206
  rect 1.397x1.651 smd: 1(-1.397,0) 2(1.397,0)
C1210
  rect 1.397x2.413 smd: 1(-1.397,0) 2(1.397,0)
D0603
  rect 0.762x0.813 smd: 1(-0.762,0) 2(0.762,0)
DFN8-1_25-5_0X3_0-H1_0
  rect 0.61x1.118 smd: 1(-1.875,-1.1) 2(-0.625,-1.1) 3(0.625,-1.1) 4(1.875,-1.1) 5(1.875,1.1) 6(0.625,1.1) 7(-0.625,1.1) 8(-1.875,1.1)
FB0603
  rect 0.762x0.813 smd: 1(-0.762,0) 2(0.762,0)
HD10-2_54
  round 1.524 hole 1.016: 1(-5.08,-1.27) 2(-5.08,1.27) 3(-2.54,-1.27) 4(-2.54,1.27) 5(0,-1.27) 6(0,1.27) 7(2.54,-1.27) 8(2.54,1.27) 9(5.08,-1.27) 10(5.08,1.27)
HD20-2_54
  rect 1.524x1.524 hole 1.016: 1(-11.43,-1.27)
  round 1.524 hole 1.016: 2(-11.43,1.27) 3(-8.89,-1.27) 4(-8.89,1.27) 5(-6.35,-1.27) 6(-6.35,1.27) 7(-3.81,-1.27) 8(-3.81,1.27) 9(-1.27,-1.27) 10(-1.27,1.27) 11(1.27,-1.27) 12(1.27,1.27) 13(3.81,-1.27) 14(3.81,1.27) 15(6.35,-1.27) 16(6.35,1.27) 17(8.89,-1.27) 18(8.89,1.27) 19(11.43,-1.27) 20(11.43,1.27)
HD40-2_0
  rect 1.422x1.422 hole 0.914: 1(-19,-1)
  round 1.422 hole 0.914: 2(-19,1) 3(-17,-1) 4(-17,1) 5(-15,-1) 6(-15,1) 7(-13,-1) 8(-13,1) 9(-11,-1) 10(-11,1) 11(-9,-1) 12(-9,1) 13(-7,-1) 14(-7,1) 15(-5,-1) 16(-5,1) 17(-3,-1) 18(-3,1) 19(-1,-1) 20(-1,1) 21(1,-1) 22(1,1) 23(3,-1) 24(3,1) 25(5,-1) 26(5,1) 27(7,-1) 28(7,1) 29(9,-1) 30(9,1) 31(11,-1) 32(11,1) 33(13,-1) 34(13,1) 35(15,-1) 36(15,1) 37(17,-1) 38(17,1) 39(19,-1) 40(19,1)
HOLE315-157
  round 8.001 hole 3.988: 1(0,0)
L4-0805
  rect 0.889x0.559 smd: 1(-0.825,-0.4) 2(0.825,-0.4) 3(0.825,0.4) 4(-0.825,0.4)
L1008
  rect 1.397x2.032 smd: 1(-1.27,0) 2(1.27,0)
QFN16-050-0303LH
  oval 0.254x0.762 smd: 1(-0.75,-1.525) 2(-0.25,-1.525) 3(0.25,-1.525) 4(0.75,-1.525) 9(0.75,1.525) 10(0.25,1.525) 11(-0.25,1.525) 12(-0.75,1.525)
  oval 0.762x0.254 smd: 5(1.525,-0.75) 6(1.525,-0.25) 7(1.525,0.25) 8(1.525,0.75) 13(-1.525,0.75) 14(-1.525,0.25) 15(-1.525,-0.25) 16(-1.525,-0.75)
  rect 1.727x1.727 smd: 17(0,0)
R0402
  rect 0.635x0.508 smd: 1(-0.508,0) 2(0.508,0)
RN8-0402
  rect 0.305x0.559 smd: 1(-0.762,-0.483) 4(0.762,-0.483) 5(0.762,0.483) 8(-0.762,0.483)
  rect 0.254x0.559 smd: 2(-0.254,-0.483) 3(0.254,-0.483) 6(0.254,0.483) 7(-0.254,0.483)
SD12-47219-2001
  rect 0.813x1.524 smd: 1(0,0) 2(-1.1,0) 3(-2.2,0) 4(-3.3,0) 5(-4.4,0) 6(-5.5,0) 7(-6.6,0) 8(-7.7,0)
  rect 1.524x2.032 smd: 9(-10.075,-2.6) 10(3.675,-2.6) 11(-10.075,5.7) 12(3.675,5.7)
SIP2-2_54
  rect 1.524x1.524 hole 1.016: 1(1.27,0)
  round 1.524 hole 1.016: 2(-1.27,0)
SLP1006P2T
  rect 0.559x0.711 smd: 1(-0.425,0) 2(0.425,0)
SOP8-50-157
  rect 0.635x1.778 smd: 1(-1.905,-2.7) 2(-0.635,-2.7) 3(0.635,-2.7) 4(1.905,-2.7) 5(1.905,2.7) 6(0.635,2.7) 7(-0.635,2.7) 8(-1.905,2.7)
SOP20-26-173
  rect 0.305x1.524 smd: 1(-2.925,-2.921) 2(-2.275,-2.921) 3(-1.625,-2.921) 4(-0.975,-2.921) 5(-0.325,-2.921) 6(0.325,-2.921) 7(0.975,-2.921) 8(1.625,-2.921) 9(2.275,-2.921) 10(2.925,-2.921) 11(2.925,2.921) 12(2.275,2.921) 13(1.625,2.921) 14(0.975,2.921) 15(0.325,2.921) 16(-0.325,2.921) 17(-0.975,2.921) 18(-1.625,2.921) 19(-2.275,2.921) 20(-2.925,2.921)
SOT23-3-095-3X1_4
  rect 0.762x1.016 smd: 1(-0.955,-1.05) 2(0.955,-1.05) 3(0,1.05)
SOT23-5-095-2_9X1_6
  rect 0.635x1.27 smd: 1(-0.95,-1.25) 2(0,-1.25) 3(0.95,-1.25) 4(0.95,1.25) 5(-0.95,1.25)
SOT23-6-095-2_9X1_6
  rect 0.635x1.143 smd: 1(-0.95,-1.22) 2(0,-1.22) 3(0.95,-1.22) 4(0.95,1.22) 5(0,1.22) 6(-0.95,1.22)
SW4-0403
  rect 1.016x0.762 smd: 1(-2.075,1.075) 2(2.075,1.075) 3(-2.075,-1.075) 4(2.075,-1.075)
SW16-1_27MM-4_55
  rect 0.762x1.245 smd: 1(-4.445,-3.072) 2(-3.175,-3.072) 3(-1.905,-3.072) 4(-0.635,-3.072) 5(0.635,-3.072) 6(1.905,-3.072) 7(3.175,-3.072) 8(4.445,-3.072) 9(4.445,3.072) 10(3.175,3.072) 11(1.905,3.072) 12(0.635,3.072) 13(-0.635,3.072) 14(-1.905,3.072) 15(-3.175,3.072) 16(-4.445,3.072)
TC7343
  rect 2.667x2.413 smd: 1(-3.233,0) 2(3.233,0)
unnamed#2
  round 1.016 smd: 1(0,0)
USB4-AF
  round 1.27 hole 0.914: 1(-3.5,1.3) 2(-1,1.3) 3(1,1.3) 4(3.5,1.3)
  round 2.794 hole 2.286: S1(-6.57,-1.41) S2(6.57,-1.41)
X4-3225
  rect 1.397x1.27 smd: 1(-1.1,-0.85) 2(1.1,-0.85) 3(1.1,0.85) 4(-1.1,0.85)

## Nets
GND: C1.2 C2.2 C4.2 C5.2 C6.2 C7.2 C8.2 C9.2 C10.2 C11.2 C12.2 C13.2 C14.2 C15.2 C16.2 C17.2 C18.2 C19.2 C20.2 C21.2 C22.2 C23.2 C24.2 C25.2 C26.2 C27.2 C28.2 C29.2 C30.2 C31.2 C32.2 C33.2 C34.2 C35.2 C36.2 C37.2 C38.2 C39.2 C40.2 C41.2 C42.2 C43.2 C44.2 C45.2 C46.2 C47.2 C48.2 C49.2 C50.2 C51.2 C52.2 C53.2 C54.2 C55.2 C56.2 C57.2 C58.2 C59.2 C60.2 C61.2 C62.2 C63.2 C64.2 C65.2 C66.2 C67.2 C68.2 C69.2 C70.2 C71.2 C72.2 C73.2 C74.2 C75.2 C76.2 C77.2 C78.2 C79.2 C80.2 C81.2 C82.2 C83.2 C84.2 C85.2 C86.2 C87.2 C88.1 C89.2 C90.2 C91.2 C92.2 C93.2 C94.2 C95.2 C96.2 C97.2 C98.2 C99.2 C100.2 C101.2 C102.2 C103.2 C104.2 C105.2 C106.2 C107.2 C108.2 C109.2 C110.2 C111.2 C112.2 C113.2 C114.2 CN1.6(VSS1) CN1.9(VSS2) CN1.10(VSS3) CN1.11(VSS4) CN1.12(VSS5) D2.1 D3.1 D4.1 D5.1 D7.1 H1.1 H2.1 H3.1 H4.1 J1.1 J1.3 J1.5 J1.7 J1.11 J1.16 J1.21 J1.26 J1.31 J1.36 J2.3 J2.8 J2.13 J2.18 J2.23 J2.28 J2.34 J2.36 J2.38 J2.40 J3.3(A2) J3.5(A3) J3.15(A8) J3.17(A9) J3.19(A10) J5.4(GND) J5.S1(SGND1) J5.S2(SGND2) J6.2(B1) J6.10(B5) R6.2 R9.2 R12.2 R13.2 R14.2 R30.2 R32.2 R34.2 R36.2 R37.1 R42.2 R52.2 R59.2 R63.1 R67.2 R73.2 R74.1 R76.1 R77.1 R78.1 R83.1 R89.2 R90.2 R91.2 R92.2 R93.2 RA1.1 RA1.2 RA1.3 RA1.4 RA2.1 RA2.2 RA2.3 RA2.4 RA3.2 RA3.3 RA3.4 RA4.2 RA4.4 RA5.1 RA5.2 RA5.3 RA5.4 RA6.2 RA6.3 RA6.4 SW1.3 SW1.4 SW2.3 SW2.4 U2.A1(VSS2) U2.A20(VSS3) U2.B3(VSS4) U2.B5(VSS5) U2.B8(VSS6) U2.B11(VSS7) U2.B13(VSS8) U2.B16(VSS9) U2.B19(VSS10) U2.C2(VSS11) U2.D17(VSS12) U2.E5(VSS13) U2.E8(VSS14) U2.E11(VSS15) U2.E14(VSS16) U2.E19(VSS17) U2.F2(VSS18) U2.G8(VSS42) U2.G10(VSS52) U2.G12(VSS64) U2.G14(VSS74) U2.G17(VSS19) U2.H4(VSS20) U2.H7(VSS38) U2.H9(VSS46) U2.H11(VSS58) U2.H13(VSS70) U2.H19(VSS35) U2.J2(VSS21) U2.J8(VSS43) U2.J9(VSS47) U2.J10(VSS53) U2.J11(VSS59) U2.J12(VSS65) U2.J14(VSS76) U2.J18(VSS22) U2.K7(VSS39) U2.K9(VSS48) U2.K10(VSS54) U2.K11(VSS60) U2.K12(VSS66) U2.K13(VSS71) U2.L8(VSS44) U2.L9(VSS49) U2.L10(VSS55) U2.L11(VSS61) U2.L12(VSS67) U2.L14(VSS75) U2.L19(VSS36) U2.M2(VSS23) U2.M4(VSS24) U2.M7(VSS40) U2.M9(VSS50) U2.M10(VSS56) U2.M11(VSS62) U2.M12(VSS68) U2.M13(VSS72) U2.M18(VSS25) U2.N8(VSS45) U2.N10(VSS57) U2.N12(VSS69) U2.N14(VSS77) U2.P7(VSS41) U2.P9(VSS51) U2.P11(VSS63) U2.P13(VSS73) U2.P19(VSS37) U2.R2(VSS26) U2.R5(VSS12_AFE) U2.R18(VSS27) U2.T1(EXT_POR) U2.T3(TEST) U2.T13(EXT_TAMPER2/EXT_WM0_TAMPER_IN) U2.T14(EXT_TAMPER0) U2.U3(VREFL_ADC) U2.U7(VSS28) U2.U10(EXT_TAMPER5/EXT_WM1_TAMPER_OUT) U2.U11(VSS_KEL0) U2.U12(EXT_TAMPER4/EXT_WM1_TAMPER_IN) U2.U13(EXT_TAMPER3/EXT_WM0_TAMPER_OUT) U2.U14(EXT_TAMPER1) U2.U19(VSS29) U2.V2(VSSA33_ADC) U2.V4(VSSA33_AFE) U2.V10(USB0_GND) U2.V11(VSS1) U2.V13(VSS30) U2.V17(VSS32) U2.W6(VSS31) U2.W12(XTAL32) U2.Y1(VSS33) U2.Y9(USB1_GND) U2.Y20(VSS34) U3.A9(VSS1) U3.B1(VSSQ1) U3.B3(VSS2) U3.B9(VSSQ2) U3.D1(VSSQ3) U3.D8(VSSQ4) U3.E1(VSS3) U3.E2(VSSQ5) U3.E8(VSSQ6) U3.F9(VSSQ7) U3.G1(VSSQ8) U3.G8(VSS4) U3.G9(VSSQ9) U3.J2(VSS5) U3.J8(VSS6) U3.M1(VSS7) U3.M9(VSS8) U3.P1(VSS9) U3.P9(VSS10) U3.T1(VSS11) U3.T9(VSS12) U4.C5(VSS1) U4.F7(VSS2) U4.K3(VSS3) U4.K8(VSS4) U5.3(GND) U5.4(CSB0) U5.5(CSB1) U7.2 U8.2 U9.1(GND) U10.2 U11.A1(GND__A1) U11.A13(GND__A13) U11.B8(GND__B8) U11.C3(GND__C3) U11.D2(GND__D2) U11.D5(GND__D5) U11.E2(GND__E2) U11.E11(GND__E11) U11.E13(IO_6_E13/CLK3N/DIFFIO_RX_R16N) U11.F3(GND__F3) U11.F10(IO_6_F10/DPCLK2/DIFFIO_RX_R26N) U11.F13(IO_6_F13/CLK3P/DIFFIO_RX_R16P) U11.G5(IO_2_G5/CLK0N/DIFFIO_RX_L18N) U11.G7(GND__G7) U11.G9(IO_6_G9/CLK2P/DIFFIO_RX_R14P) U11.G10(IO_6_G10/CLK2N/DIFFIO_RX_R14N) U11.H4(IO_2_H4/CLK1P/DIFFIO_RX_L20P) U11.H5(IO_2_H5/CLK1N/DIFFIO_RX_L20N) U11.H12(GND__H12) U11.J4(GND__J4) U11.L9(GND__L9) U11.M6(GND__M6) U11.N1(GND__N1) U11.N3(IO_2_N3/DPCLK1/DIFFIO_RX_L22P) U11.N13(GND__N13) U14.6(AGND) U14.7(FSW) U14.8(DEF) U14.15(PGND1) U14.16(PGND2) U14.17(PWR_PAD) U15.10(GND) U15.11(B8) U15.12(B7) U15.13(B6) U15.14(B5) U15.15(B4) U15.16(B3) U16.1(DIR) U16.10(GND) U16.11(B8) U16.12(B7) U16.13(B6) U16.14(B5) U16.19(*OE) U17.2(GND) U18.2(GND) X1.2(GND) Y1.2(GND1) Y1.4(GND2)
VBUS: C89.1 FB4.1 J5.1(VCC) U10.5
VCC: C2.1 C90.1 FB7.1 J1.2 J1.4 J4.1(A1) R61.2 U9.2(IN)
VCC_1V1: C61.1 C62.1 U2.V12(DECAP_V11_LDO_OUT)
VCC_2V5_SDRAM: C44.1 C45.1 C46.1 C47.1 C59.1 U2.E6(SDRAMC_VDD2P5_2) U2.E10(SDRAMC_VDD2P5_3) U2.J5(SDRAMC_VDD2P5_1) U2.T11(DECAP_V25_LDO_OUT)
VCC_3V3_ADC: C85.1 C86.1 FB2.1 U2.V1(VDDA33_ADC)
VCC_3V3_MCULDO: C82.1 C83.1 U2.Y10(USB_DCAP)
VDD12: C48.1 C49.1 C50.1 C51.1 C52.1 C53.1 C54.1 C55.1 C56.1 C57.1 C58.1 C60.1 Q1.2(EMITTER) U2.G7(VDD1) U2.G9(VDD8) U2.G11(VDD12) U2.G13(VDD16) U2.H8(VDD4) U2.H10(VDD10) U2.H12(VDD14) U2.H14(VDD20) U2.J7(VDD2) U2.J13(VDD17) U2.K8(VDD5) U2.K14(VDD21) U2.L7(VDD3) U2.L13(VDD18) U2.M8(VDD6) U2.M14(VDD22) U2.N7(FA_VDD) U2.N9(VDD9) U2.N11(VDD13) U2.N13(VDD19) U2.P8(VDD7) U2.P10(VDD11) U2.P12(VDD15) U2.P14(VDD23)
VDD12_AFE: U2.T5(VDD12_AFE)
VDD15: C3.1 C7.1 C8.1 C9.1 C10.1 C11.1 C12.1 C13.1 C14.1 C15.1 C16.1 C17.1 C18.1 C19.1 C20.1 C21.1 C22.1 C23.1 C24.1 C38.1 C39.1 C40.1 C41.1 C42.1 C43.1 C79.1 C111.1 L2.2 Q1.3(COLLECTOR) R8.1 R11.1 R87.2 R88.1 U2.D5(SDRAMC_VDD1P5_2) U2.D11(SDRAMC_VDD1P5_8) U2.E4(SDRAMC_VDD1P5_1) U2.E7(SDRAMC_VDD1P5_6) U2.E9(SDRAMC_VDD1P5_7) U2.F5(SDRAMC_VDD1P5_3) U2.H5(SDRAMC_VDD1P5_4) U2.K5(SDRAMC_VDD1P5_5) U3.A1(VDDQ1) U3.A8(VDDQ2) U3.B2(VDD1) U3.C1(VDDQ3) U3.C9(VDDQ4) U3.D2(VDDQ5) U3.D9(VDD2) U3.E9(VDDQ6) U3.F1(VDDQ7) U3.G7(VDD3) U3.H2(VDDQ8) U3.H9(VDDQ9) U3.K2(VDD4) U3.K8(VDD5) U3.N1(VDD6) U3.N9(VDD7) U3.R1(VDD8) U3.R9(VDD9) U14.14(VOS)
VDD33: C1.1 C25.1 C26.1 C27.1 C28.1 C36.1 C63.1 C64.1 C65.1 C66.1 C67.1 C68.1 C69.1 C70.1 C71.1 C72.1 C73.1 C74.1 C75.1 C76.1 C87.1 C88.2 C93.1 C95.1 C96.1 C97.1 C98.1 C99.1 C100.1 C105.1 C106.1 C107.1 C108.1 C109.1 C110.1 CN1.4(VDD) D2.2 D3.2 D4.2 FB1.2 FB2.2 FB3.2 FB5.2 FB6.1 J1.6 J1.8 J3.1(A1) J6.4(B2) R1.2 R2.2 R3.2 R4.2 R5.2 R15.1 R16.1 R17.1 R27.2 R29.1 R31.1 R33.1 R35.1 R46.1 R47.2 R48.2 R49.2 R50.2 R53.1 R54.1 R55.1 R56.1 R57.1 R58.1 R60.2 R69.1 R70.2 R71.2 R75.2 R79.1 R80.1 R81.1 R82.1 R84.1 R85.1 RA3.1 RA4.1 RA4.3 RA7.1 RA7.2 RA7.3 RA7.4 S1.9 S1.10 S1.11 S1.12 S1.13 S1.14 S1.15 S1.16 U2.C12(VDD33_4) U2.C15(VDD33_5) U2.C18(VDD33_10) U2.F18(VDD33_11) U2.K3(VDD33_1) U2.K17(VDD33_7) U2.N3(VDD33_2) U2.N17(VDD33_8) U2.P5(VDDREG) U2.T12(VDD33_LDOIN) U2.T17(VDD33_9) U2.U16(VDD33_6) U2.V8(VDD33_3) U2.V14(VBAT) U2.W18(VDD33_12) U4.D3(VCC1) U4.G4(VCC2) U4.H8(VCC3) U4.J6(VCC4) U8.4 U11.C6(VCCIO8__C6) U11.C7(VCCIO8__C7) U11.C8(VCCIO8__C8) U11.F2(VCCIO1A__F2) U11.F7(VCC_ONE__F7) U11.F11(VCCIO6__F11) U11.G3(VCCIO1B__G3) U11.G6(VCC_ONE__G6) U11.G8(VCC_ONE__G8) U11.G11(VCCIO6__G11) U11.H7(VCC_ONE__H7) U11.H11(VCCIO5__H11) U11.J3(VCCIO2__J3) U11.J11(VCCIO5__J11) U11.K3(VCCIO2__K3) U11.L6(VCCIO3__L6) U11.L7(VCCIO3__L7) U11.L8(VCCIO3__L8) U15.20(VCC) U16.20(VCC) U17.5(VDD) U18.5(VDD)
VDDA33_AFE: U2.V3(VDDA33_AFE)
AD0: J2.39 R38.2
AD1: J2.37 R39.2
AD2: J2.35 R40.2
BCTRL: Q1.1(BASE) U2.T2(BCTRL)
BOARD_ID0: R29.2 R30.1 U2.T15(PTC9/RMII1_MDC/ESAI_SCKT)
BOARD_ID1: R31.2 R32.1 U2.U15(PTC10/RMII1_MDIO/ESAI_FST)
BOARD_ID2: R33.2 R34.1 U2.P4(PTC11/RMII1_CRS_DV/ESAI_SDO0)
BOARD_ID3: R35.2 R36.1 U2.P3(PTC12/RMII1_RXD1/ESAI_SDO1/SAI2)
BOOT_SEL: R74.2 R75.1 U11.D7(IO_8_D7/BOOT_SEL)
BOOTMOD0: RA1.5 S1.1 U2.N18(PTE1/DCU0_VSYNC/DCU0_TCON2/BOOT)
BOOTMOD1: RA1.6 S1.2 U2.N16(PTE0/DCU0_HSYNC/DCU0_TCON1/BOOT)
CAN_RX: J1.18 U2.B14(PTB14/CAN0_RX/I2C0_SCL)
CAN_TX: J1.17 R26.1
CPU_RST_N: C37.1 R47.1 R51.1 R66.1 U18.3(*MR)
DDR_A0: U2.C7(DDR_A0) U3.N3(A0)
DDR_A1: U2.C11(DDR_A1) U3.P7(A1)
DDR_A2: U2.A8(DDR_A2) U3.P3(A2)
DDR_A3: U2.B7(DDR_A3) U3.N2(A3)
DDR_A4: U2.A6(DDR_A4) U3.P8(A4)
DDR_A5: U2.B6(DDR_A5) U3.P2(A5)
DDR_A6: U2.A9(DDR_A6) U3.R8(A6)
DDR_A7: U2.A7(DDR_A7) U3.R2(A7)
DDR_A8: U2.A11(DDR_A8) U3.T8(A8)
DDR_A9: U2.B9(DDR_A9) U3.R3(A9)
DDR_A10: U2.D7(DDR_A10) U3.L7(A10/AP)
DDR_A11: U2.D10(DDR_A11) U3.R7(A11)
DDR_A12: U2.C10(DDR_A12) U3.N7(A12/B\C\)
DDR_BA0: U2.C8(DDR_BA0) U3.M2(BA0)
DDR_BA1: U2.C9(DDR_BA1) U3.N8(BA1)
DDR_BA2: U2.D8(DDR_BA2) U3.M3(BA2)
DDR_CAS_B: U2.B4(D\D\R\_\C\A\S\) U3.K3(C\A\S\)
DDR_CKE: R14.1 U2.A5(DDR_CKE0) U3.K9(CKE)
DDR_CLK: R10.1 U2.A2(DDR_CLK0) U3.J7(CK)
DDR_CLK_B: R10.2 U2.B2(D\D\R\_\C\L\K\0\) U3.K7(C\K\)
DDR_CS_B: U2.C5(D\D\R\_\C\S\0\) U3.L2(C\S\)
DDR_D0: U2.F4(DDR_D0) U3.E3(DQL0)
DDR_D1: U2.H3(DDR_D1) U3.F7(DQL1)
DDR_D2: U2.D4(DDR_D2) U3.F2(DQL2)
DDR_D3: U2.G4(DDR_D3) U3.F8(DQL3)
DDR_D4: U2.F3(DDR_D4) U3.H3(DQL4)
DDR_D5: U2.J3(DDR_D5) U3.H8(DQL5)
DDR_D6: U2.C3(DDR_D6) U3.G2(DQL6)
DDR_D7: U2.G3(DDR_D7) U3.H7(DQL7)
DDR_D8: U2.J1(DDR_D8) U3.D7(DQU0)
DDR_D9: U2.D1(DDR_D9) U3.C3(DQU1)
DDR_D10: U2.H1(DDR_D10) U3.C8(DQU2)
DDR_D11: U2.E2(DDR_D11) U3.C2(DQU3)
DDR_D12: U2.G1(DDR_D12) U3.A7(DQU4)
DDR_D13: U2.C1(DDR_D13) U3.A2(DQU5)
DDR_D14: U2.H2(DDR_D14) U3.B8(DQU6)
DDR_D15: U2.D2(DDR_D15) U3.A3(DQU7)
DDR_DQM0: U2.J4(DDR_DQM0) U3.E7(DML)
DDR_DQM1: U2.G2(DDR_DQM1) U3.D3(DMU)
DDR_DQS0: U2.D3(DDR_DQS0) U3.F3(DQSL)
DDR_DQS0_B: U2.E3(D\D\R\_\D\Q\S\0\) U3.G3(D\Q\S\L\)
DDR_DQS1: U2.E1(DDR_DQS1) U3.C7(DQSU)
DDR_DQS1_B: U2.F1(D\D\R\_\D\Q\S\1\) U3.B7(D\Q\S\U\)
DDR_ODT0: U2.C4(DDR_ODT0) U3.K1(ODT)
DDR_ODT1: U2.B1(DDR_ODT1)
DDR_RAS_B: U2.A4(D\D\R\_\R\A\S\) U3.J3(R\A\S\)
DDR_RESET: R11.2 U2.D6(DDR_RESET) U3.T2(R\E\S\E\T\)
DDR_WE_B: U2.C6(D\D\R\_\W\E\) U3.L3(W\E\)
DDR_ZQ_M: R12.1 U2.A3(DDR_ZQ)
DDR_ZQ_S: R13.1 U3.L8(ZQ)
EXTAL_MAIN: C31.1 U2.Y13(EXTAL) Y1.1
FPGA_CLK: R68.1 U11.H6(IO_2_H6/CLK0P/DIFFIO_RX_L18P)
FPGA_RST_N: C92.1 R69.2 U11.F9(IO_6_F9/DPCLK3/DIFFIO_RX_R26P) U11.N2(IO_2_N2/DPCLK0/DIFFIO_RX_L22N) U17.4(*RESET)
I2C_SCL_BARAMETRIC: R49.1 U2.C14(PTB16/CAN1_RX/I2C1_SCL) U5.8(SCLK)
I2C_SDA_BARAMETRIC: R48.1 U2.A15(PTB17/CAN1_TX/I2C1_SDA) U5.7(SDI/SDA)
ID0: J1.9 R27.1 U2.L2(PTC4/RMII0_RXD0/SCI1_RTS/DSPI1_)
ID1: J1.10 RA7.5 U2.M1(PTC5/RMII0_RXER/SCI1_CTS/DSPI1_)
ID3: J1.12 RA7.6 U2.N1(PTC6/RMII0_TXD1/DSPI1_SIN/ESAI_)
ID4: J1.13 RA7.7 U2.N2(PTC7/RMII0_TXD0/DSPI1_SOUT/ESAI)
ID5: J1.14 RA7.8 U2.N4(PTC8/RMII0_TXEN/DSPI1_SCK)
JTAG_TCK: J6.1(A1) R83.2 U16.17(B2)
JTAG_TDI: J6.9(A5) R85.2 U16.16(B3)
JTAG_TDO: J6.3(A2) U16.5(A4)
JTAG_TMS: J6.5(A3) R84.2 U16.18(B1)
JTCLK: J3.4(B2) U2.K4(PTA8/JTCLK/SWCLK)
JTDI: J3.8(B4) U2.K2(PTA9/JTDI/RMII_CLKOUT/RMII_CLKI)
JTDO: J3.6(B3) U2.K1(PTA10/JTDO/EXT_AUDIO_MCLK/ENET_)
JTMS: J3.2(B1) U2.L1(PTA11/JTMS/SWDIO)
NC_DDR_A13: U2.A10(DDR_A13)
NC_DDR_A14: U2.D9(DDR_A14)
NC_DDR_A15: U2.B10(DDR_A15)
NF_ALE: U2.E16(PTC27/SAI1_RX_BCLK/DSPI0_PCS4/R) U4.C4(ALE)
NF_CE_N: R16.2 U2.B17(PTB25/SAI0_RX_DATA/SCI1_RTS/RCO) U4.C6(NCE) U15.2(A1)
NF_CLE: U2.E15(PTC28/SAI1_RX_DATA/DSPI0_PCS3/R) U4.D5(CLE)
NF_IO0: U2.D20(PTD16/NF_IO0/ESAI_HCKT) U4.H4(IO0)
NF_IO1: U2.E20(PTD17/NF_IO1/ESAI_HCKR) U4.J4(IO1)
NF_IO2: U2.E18(PTD18/NF_IO2/ESAI_FSR/FTM2_QD_P) U4.K4(IO2)
NF_IO3: U2.F16(PTD19/NF_IO3/ESAI_SCKR/FTM2_QD_) U4.K5(IO3)
NF_IO4: U2.F17(PTD20/NF_IO4/ENET0_1588_TMR3/SD) U4.K6(IO4)
NF_IO5: U2.F19(PTD21/NF_IO5/ENET0_1588_TMR2/SD) U4.J7(IO5)
NF_IO6: U2.F20(PTD22/NF_IO6/FTM2CH1/ENET0_1588) U4.K7(IO6)
NF_IO7: U2.G20(PTD23/NF_IO7/FTM2CH0/ENET0_1588) U4.J8(IO7)
NF_IO8: U2.G19(PTD24/NF_IO8/FTM3CH7) U4.H3(IO8)
NF_IO9: U2.G18(PTD25/NF_IO9/FTM3CH6) U4.J3(IO9)
NF_IO10: U2.G16(PTD26/NF_IO10/FTM3CH5/SDHC1_WP) U4.H5(IO10)
NF_IO11: U2.H16(PTD27/NF_IO11/FTM3CH4/DSPI2_SCK) U4.J5(IO11)
NF_IO12: U2.H17(PTD28/NF_IO12/FTM3CH3/DSPI2_SOU) U4.H6(IO12)
NF_IO13: U2.H18(PTD29/NF_IO13/FTM3CH2/DSPI2_SIN) U4.G6(IO13)
NF_IO14: U2.H20(PTD30/NF_IO14/FTM3CH1/DSPI2_PCS) U4.H7(IO14)
NF_IO15: U2.J20(PTD31/NF_IO15/FTM3CH0/DSPI2_PCS) U4.G7(IO15)
NF_RB_N: R17.2 U2.D16(PTC26/SAI1_TX_BCLK/DSPI0_PCS5/R) U4.C8(NR/B)
NF_RE_N: U2.U8(PTB27/SAI0_RX_SYNC/RCON22/N\F\_) U4.D4(NRE) U15.3(A2)
NF_WE_N: U2.A18(PTB24/SAI0_RX_BCLK/SCI1_RX/RCON) U4.C7(WE#)
PTA20: R24.2 U2.B18(PTA20/TRACED4/SCI3_TX)
PTA30: U2.P17(PTA30/TRACED14/SAI3_RX_SYNC/ENE) U11.B7(IO_8_B7/VREFB8N0)
PTA31: U2.P16(PTA31/TRACED15/SAI3_TX_SYNC/ENE) U11.E8(IO_8_E8/DIFFIO_RX_T18N)
PTB0: U2.T6(PTB0/FTM0CH0/ADC0SE2/TRACECTL/S) U11.A2(IO_8_A2/DIFFIO_RX_T26P)
PTB3: U2.W7(PTB3/FTM0CH3/ADC1SE3/EXTRIG) U11.A5(IO_8_A5/DIFFIO_RX_T25P)
PTB4: U2.Y7(PTB4/FTM0CH4/SCI1_TX/ADC0SE4) U11.B4(IO_8_B4/DIFFIO_RX_T23N)
PTB5: U2.Y8(PTB5/FTM0CH5/SCI1_RX/ADC1SE4) U11.B3(IO_8_B3/DIFFIO_RX_T23P)
PTB6: U2.W8(PTB6/FTM0CH6/SCI1_RTS/SCI2_TX) U11.E6(IO_8_E6/DIFFIO_RX_T22P)
PTB7: U2.D13(PTB7/FTM0CH7/SCI1_CTS/SCI2_RX) U11.A3(IO_8_A3/DIFFIO_RX_T21N)
PTB8: U2.J16(PTB8/FTM1CH0/FTM1_QD_PHA) U11.B5(IO_8_B5/DIFFIO_RX_T20N)
PTB9: U2.J19(PTB9/FTM1CH1/FTM1_QD_PHB) U11.A4(IO_8_A4/DIFFIO_RX_T21P)
PTB10: R25.2 U2.B15(PTB10/SCI0_TX/CKO1 /ENET_TS_CLK)
PTB15: R26.2 U2.A14(PTB15/CAN0_TX/I2C0_SDA)
PTC2: R28.2 U2.M5(PTC2/RMII0_CRS_DV/SCI1_TX/ESAI_)
PTC31: D1.1(ATHODE) U2.W5(PTC31/SAI1_TX_SYNC/RCON29/ADC1S)
PTD0: R20.1 U2.Y17(PTD0/QSPI0_A_SCK/SCI2_TX/SPDIF_)
PTD4: R21.1 U2.W19(PTD4/QSPI0_A_DATA1/DSPI1_PCS1/S)
PTD5: R18.1 U2.W20(PTD5/QSPI0_A_DATA0/DSPI1_PCS0)
PTD7: R22.1 U2.V19(PTD7/QSPI0_B_SCK/DSPI1_SOUT)
PTD8: R23.1 U2.U17(PTD8/QSPI0_B_CS0/DSPI1_SCK)
RCON0: RA2.6 S1.6 U2.M20(PTE7/DCU0_R2/RCON0)
RCON1: RA2.7 S1.7 U2.M19(PTE8/DCU0_R3/RCON1)
RCON2: RA2.8 S1.8 U2.M17(PTE9/DCU0_R4/RCON2)
RCON3: RA3.5 U2.M16(PTE10/DCU0_R5/RCON3)
RCON4: RA3.6 U2.L16(PTE11/DCU0_R6/RCON4)
RCON5: RA1.7 S1.3 U2.L17(PTE12/DCU0_R7/DSPI1_PCS3/RCON5/)
RCON6: RA1.8 S1.4 U2.L18(PTE15/DCU0_G2/RCON6)
RCON7: RA2.5 S1.5 U2.L20(PTE16/DCU0_G3/RCON7)
RCON8: RA3.7 U2.K20(PTE17/DCU0_G4/RCON8)
RCON9: RA3.8 U2.K19(PTE18/DCU0_G5/RCON9)
RCON10: R1.1 RA4.5 U2.K18(PTE19/DCU0_G6/RCON10)
RCON11: RA4.6 U2.A12(PTE20/DCU0_G7/RCON11/EWM_IN)
RCON12: R2.1 RA4.7 U2.J17(PTE23/DCU0_B2/RCON12)
RCON13: RA4.8 U2.D19(PTE24/DCU0_B3/RCON13)
RCON14: RA5.5 U2.C19(PTE25/DCU0_B4/RCON14)
RCON15: U2.C20(PTE26/DCU0_B5/RCON15)
RCON16: U2.B20(PTE27/DCU0_B6/RCON16)
RCON17: U2.K16(PTE28/DCU0_B7/RCON17/EWM_OUT)
RCON18: R3.1 RA5.6 U2.L4(PTC0/RMII0_MDC/FTM1CH0/DSPI0_PC)
RCON20: R4.1 RA5.7 U15.18(B1)
RCON21: R5.1 RA5.8 U2.A17(PTB26/SAI0_TX_DATA/SCI1_CTS/RCO)
RCON22: RA6.5 U15.17(B2)
RCON23: U2.A16(PTB28/SAI0_TX_SYNC/RCON23)
RCON30: RA6.6 U2.T7(PTB1/FTM0CH1/ADC0SE3/RCON30/SAI)
RCON31: RA6.7 U2.V7(PTB2/FTM0CH2/ADC1SE2/RCON31/SAI)
RESET_B: C34.1 J3.10(B5) R7.2 R46.2 U2.T4(R\E\S\E\T\/RESET_OUT) U18.4(*RESET)
SAFE_MODE_EN_N: J1.15 U2.T18(PTD13/QSPI0_B_DQS/DSPI3_SCK)
SDHC1_CD: R59.1 R60.1 U2.V15(PTA7)
SDHC1_CLK: CN1.5(CLK) R19.1 R56.2 U7.6
SDHC1_CMD: CN1.3(CMD) R55.2 U2.R17(PTA25/TRACED9/USB1_VBUS_OC/SDHC) U7.4
SDHC1_DAT0: CN1.7(DAT0) R57.2 U2.R19(PTA26/TRACED10/SAI3_TX_BCLK/SDH) U8.1
SDHC1_DAT1: CN1.8(DAT1) R58.2 U2.R20(PTA27/TRACED11/SAI3_RX_BCLK/SDH) U8.3
SDHC1_DAT2: CN1.1(DAT2) R53.2 U2.P20(PTA28/TRACED12/SAI3_RX_DATA/ENE) U7.1
SDHC1_DAT3: CN1.2(CD/DAT3) R54.2 U2.P18(PTA29/TRACED13/SAI3_TX_DATA/ENE) U7.3
SPI_CS0_FPGA: R18.2 U11.A10(IO_8_A10/DIFFIO_RX_T17P)
SPI_CS1_FPGA: R21.2 U11.A9(IO_8_A9/DIFFIO_RX_T15N)
SPI_DIN_FPGA: R64.1 U2.V20(PTD6/QSPI0_A_DQS/DSPI1_SIN)
SPI_DOUT_FPGA: R22.2 U11.A11(IO_8_A11/DIFFIO_RX_T17N)
SPI_SCK_FPGA: R23.2 U11.B10(IO_8_B10/DIFFIO_RX_T16P)
TCK_FPGA: U11.G2(IO_1B_G2/TCK/DIFFIO_RX_L11P) U16.3(A2)
TDI_FPGA: U11.F5(IO_1B_F5/TDI/DIFFIO_RX_L12N) U16.4(A3)
TDO_FPGA: U11.F6(IO_1B_F6/TDO/DIFFIO_RX_L12P) U16.15(B4)
TMS_FPGA: U11.G1(IO_1B_G1/TMS/DIFFIO_RX_L11N) U16.2(A1)
TRACE_D0: J3.14(B7) U2.Y5(PTA16/TRACED0/USB0_VBUS_EN/ADC1)
TRACE_D1: J3.16(B8) U2.Y6(PTA17/TRACED1/USB0_VBUS_OC/ADC1)
TRACE_D2: J3.18(B9) U2.V6(PTA18/TRACED2/ADC0SE0/FTM1_QD_P)
TRACE_D3: J3.20(B10) U2.U6(PTA19/TRACED3/ADC0SE1/FTM1_QD_P)
TRACECK: J3.12(B6) U2.L3(PTA12/TRACECK/EXT_AUDIO_MCLK)
UART_RX0_DEBUG: J1.20 U2.D14(PTB11/SCI0_RX/CKO2)
UART_RX1: J1.24 U2.Y18(PTD1/QSPI0_A_CS0/SCI2_RX/SPDIF_)
UART_RX2: J1.25 U2.D18(PTA21/TRACED5/SAI2_RX_BCLK/SCI3)
UART_RX3: J1.27 U11.J9(IO_5_J9/DIFFIO_RX_R8P)
UART_RX4: J1.29 U11.K10(IO_5_K10/DIFFIO_RX_R1P)
UART_RX5: J1.32 U11.J10(IO_5_J10/DIFFIO_RX_R1N)
UART_RX6: J1.33 U11.H13(IO_5_H13/DIFFIO_RX_R9N)
UART_RX7: J1.37 U11.J12(IO_5_J12/DIFFIO_RX_R7N)
UART_RX8: J1.39 U11.H8(IO_5_H8/DIFFIO_RX_R10N)
UART_RX9: J2.7 U11.E12(IO_6_E12/DIFFIO_RX_R18N)
UART_RX10: J2.10 U11.L5(IO_3_L5/DIFFIO_TX_RX_B1N)
UART_RX11: J2.12 U11.L4(IO_3_L4/DIFFIO_TX_RX_B1P)
UART_RX12: J2.16 U11.N4(IO_3_N4/DIFFIO_RX_B4N)
UART_RX13: J2.17 U11.N5(IO_3_N5/DIFFIO_RX_B4P)
UART_RX14: J2.20 U11.N7(IO_3_N7/DIFFIO_RX_B6N)
UART_RX15: J2.22 U11.M9(IO_3_M9/DIFFIO_RX_B8P)
UART_RX16: J2.26 U11.N11(IO_3_N11/VREFB3N0)
UART_RX17: J2.27 U11.N8(IO_3_N8/DIFFIO_RX_B6P)
UART_RX18: J2.30 U11.M8(IO_3_M8/DIFFIO_RX_B8N)
UART_RX19: J2.32 U11.M13(IO_3_M13/DIFFIO_TX_RX_B10N)
UART_RX_FROM_FPGA: R65.1 U2.M3(PTC3/RMII0_RXD1/SCI1_RX/ESAI_SD)
UART_TX0_DEBUG: J1.19 R25.1
UART_TX1: J1.22 R20.2
UART_TX2: J1.23 R24.1
UART_TX3: J1.28 U11.K13(IO_5_K13/VREFB5N0)
UART_TX4: J1.30 U11.K11(IO_5_K11/DIFFIO_RX_R2P)
UART_TX5: J1.34 U11.L12(IO_5_L12/DIFFIO_RX_R2N)
UART_TX6: J1.35 U11.H9(IO_5_H9/DIFFIO_RX_R10P)
UART_TX7: J1.38 U11.L13(IO_5_L13)
UART_TX8: J1.40 U11.G12(IO_5_G12/DIFFIO_RX_R11N)
UART_TX9: J2.5 U11.F12(IO_6_F12/DIFFIO_RX_R18P)
UART_TX10: J2.9 U11.M4(IO_3_M4/DIFFIO_RX_B2N)
UART_TX11: J2.11 U11.M5(IO_3_M5/DIFFIO_RX_B2P)
UART_TX12: J2.14 U11.K5(IO_3_K5/DIFFIO_TX_RX_B3N)
UART_TX13: J2.15 U11.J5(IO_3_J5/DIFFIO_TX_RX_B3P)
UART_TX14: J2.19 U11.N6(IO_3_N6/DIFFIO_TX_RX_B5N)
UART_TX15: J2.21 U11.K6(IO_3_K6/DIFFIO_TX_RX_B7P)
UART_TX16: J2.24 U11.J7(IO_3_J7/DIFFIO_TX_RX_B9N)
UART_TX17: J2.25 U11.M7(IO_3_M7/DIFFIO_TX_RX_B5P)
UART_TX18: J2.29 U11.J6(IO_3_J6/DIFFIO_TX_RX_B7N)
UART_TX19: J2.31 U11.N12(IO_3_N12)
UART_TX_TO_FPGA: R28.1 U11.A7(IO_8_A7/DIFFIO_RX_T19P)
USB0_DN: J2.2 U2.T9(USB0_DM)
USB0_DP: J2.4 U2.T10(USB0_DP)
USB0_VBUS: C77.1 C78.1 J2.1 U2.W11(USB0_VBUS) U2.Y11(USB0_VBUS_DETECT)
USB0_VBUS_EN_N: J2.6 U2.R3(PTC16/RMII1_TXD0/ESAI_SDI1/SCI5)
USB1_DN: L1.2 U2.V9(USB1_DM)
USB1_DP: L1.3 U2.W9(USB1_DP)
USB1_VBUS: C80.1 C81.1 FB4.2 U2.U9(USB1_VBUS_DETECT) U2.W10(USB1_VBUS) U9.6(OUT2) U9.7(OUT1)
USB1_VBUS_EN_N: R62.2 U2.R4(PTC17/RMII1_TXEN/SCI5_CTS/SAI2_)
USB_N: J5.2(DATA+) L1.1 U10.1
USB_P: J5.3(DATA-) L1.4 U10.3
VREF_3V3: C84.1 FB3.1 U2.W1(VREFH_ADC)
VREF_DDR3: C3.2 C4.1 C5.1 C6.1 R8.2 R9.1 U2.G5(DDR_VREF) U3.H1(VREFDQ) U3.M8(VREFCA)
XTAL_MAIN: C30.1 R42.1 U2.W13(XTAL) Y1.3
N2153652: C112.1 C113.1 FB7.2 R86.1 U14.10(AVIN) U14.11(PVIN1) U14.12(PVIN2)
N2153712: R88.2 R89.1 U14.5(FB)
N2153966: C114.1 U14.9(SS/TR)
N2153998: L2.1 U14.1(SW1) U14.2(SW2) U14.3(SW3)
N2154070: R87.1 U14.4(PG)
N2154096: R86.2 U14.13(EN)
N2191397: R91.1 U2.U4(VADCSE1)
N2191403: R92.1 U2.W4(VADCSE2)
N2191409: R93.1 U2.V5(VADCSE3)
N2191777: U2.W14(LVDS0P)
N2191789: U2.Y14(LVDS0N)
N2191945: C32.1 D2.3 R40.1 U2.W3(ADC1SE8)
N2191949: C29.1 D3.3 R39.1 U2.W2(ADC0SE9)
N2191953: C33.1 D4.3 R38.1 U2.Y2(ADC0SE8)
N2192059: R90.1 U2.Y4(VADCSE0)
N2281272: D5.2 R51.2 SW1.1 SW1.2
N2281444: R50.1 R52.1 U18.1(CT)
N2284326: R15.2 U4.C3(NWP)
N2287958: R19.2 U2.R16(PTA24/TRACED8/USB1_VBUS_EN/SDHC)
N2289519: R61.1 U9.5(OC2_N) U9.8(OC1_N)
N2289539: R62.1 R63.2 U9.3(EN1_N) U9.4(EN2_N)
N2296270: R6.1 U15.1(DIR)
N2296455: R7.1 U15.19(*OE)
N2309411: J3.11(A6) J3.13(A7) J4.2(B1)
N2319696: C35.1 FB1.1 U5.1(VDD) U5.2(PS)
N2331782: C101.1 C102.1 C103.1 C104.1 FB6.2 U11.D3(VCCA3__D3) U11.D4(VCCA3__D4) U11.D10(VCCA2__D10) U11.K4(VCCA1__K4) U11.K9(VCCA4__K9)
N2337623: R79.2 U11.C4(IO_8_C4/NSTATUS/DIFFIO_RX_T24P)
N2337645: R80.2 U11.C5(IO_8_C5/CONF_DONE/DIFFIO_RX_T24)
N2337651: R81.2 U11.E7(INPUT_ONLY_8_E7/NCONFIG)
N2338140: R82.2 U11.E5(IO_1B_E5/JTAGEN/DIFFIO_RX_L9P)
N2350524: D1.2(CATHODEC) R37.2
N2353252: D8.1(ATHODE) U11.D6(IO_8_D6/CRC_ERROR/DIFFIO_RX_T22)
N2353538: R77.2 U11.D8(IO_8_D8/DEV_OE/DIFFIO_RX_T18P)
N2353540: R76.2 U11.B9(IO_8_B9/DEV_CLRN/DIFFIO_RX_T16N)
N2361317: C94.1 R70.1 R72.1 U17.3(*MR)
N2361377: D7.2 R72.2 SW2.1 SW2.2
N2361557: R71.1 R73.1 U17.1(CT)
N2361860: R68.2 X1.3(OUT)
N2361916: C91.1 FB5.1 X1.1(OE) X1.4(VDD)
N2362456: D6.1(ATHODE) U11.M3(IO_2_M3/PLL_L_CLKOUTN/DIFFIO_RX)
N2362502: D6.2(CATHODEC) R67.1
N2363039: R65.2 U11.A6(IO_8_A6/DIFFIO_RX_T19N)
N2363108: R64.2 U11.A8(IO_8_A8/DIFFIO_RX_T15P)
N2364591: R66.2 U11.B6(IO_8_B6/DIFFIO_RX_T20P)
N2426258: J2.33
N23532460: D8.2(CATHODEC) R78.2

Pads without a net: J3 7 9; J6 6 7 8; NOREF#10 1; NOREF#12 1; NOREF#13 1; NOREF#21 1; NOREF#22 1; NOREF#23 1; RA6 1 8; U2 A13 A19 B12 C13 C16 C17 D12 D15 E12 E13 E17 L5 N5 N19 N20 P1 P2 R1 T8 T16 T19 T20 U1 U2 U5 U18 U20 V16 V18 W15 W16 W17 Y3 Y12 Y15 Y16 Y19; U3 J1 J9 L1 L9 M7 T3 T7; U4 A1 A2 A9 A10 B1 B9 B10 D6 D7 D8 E3 E4 E5 E6 E7 E8 F3 F4 F5 F6 F8 G3 G5 G8 L1 L2 L9 L10 M1 M2 M9 M10; U5 6; U7 5; U8 5 6; U10 4 6; U11 A12 B1 B2 B11 B12 B13 C1 C2 C9 C10 C11 C12 C13 D1 D9 D11 D12 D13 E1 E3 E4 E9 E10 F1 F4 F8 G4 G13 H1 H2 H3 H10 J1 J2 J8 J13 K1 K2 K7 K8 K12 L1 L2 L3 L10 L11 M1 M2 M10 M11 M12 N9 N10; U15 4 5 6 7 8 9; U16 6 7 8 9

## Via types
v1: diameter 0.457, hole 0.203, TOP to BOTTOM, 490 vias
v2: diameter 0.559, hole 0.254, TOP to BOTTOM, 411 vias

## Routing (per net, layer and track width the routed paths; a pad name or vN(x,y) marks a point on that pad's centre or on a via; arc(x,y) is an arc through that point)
GND: length 528.7
  TOP w0.127: 22.34,67.81 v1(22.51,67.65)
  TOP w0.254: v2(25.91,36.2) 26.29,36.58 RA6.2 ; RA5.4 47.4,53.94 v2(47.62,53.72) 47.34,53.43 RA5.3 ; RA6.4 27.3,36.45 v2(27.05,36.2) 26.8,36.45 RA6.3 ; RA3.2 46.74,50.16 46.86,50.29 v2(46.86,51.05) ; RA2.1 46.61,44.07 v2(46.86,44.32) 46.61,44.58 45.95,44.58 ; U14.7 13.09,73.27 v2(12.83,73.53) 13.07,73.78 U14.8 ; RA1.1 46.61,46.86 v2(46.86,47.12) 46.61,47.37 RA1.2 ; RA5.1 47.34,52.42 v2(47.62,52.7) 47.4,52.93 RA5.2 ; v2(47.62,57.15) 47.62,57.12 47.27,56.77 RA4.4 ; RA4.2 47.24,55.75 v2(47.62,55.37) ; U16.1 49.53,29.97 49.78,29.72 v2(49.78,29.72) ; RA3.4 46.74,51.18 v2(46.86,51.05) ; v2(46.86,51.05) 46.48,50.67 RA3.3 ; RA2.3 46.61,45.09 v2(46.86,45.34) 46.61,45.59 RA2.4 ; RA1.3 46.61,47.88 v2(46.86,48.13) 46.61,48.39 RA1.4 ; U14.16 11.57,72.27 v2(11.81,72.52) 11.55,72.78 U14.15 ; U14.6 13.09,72.78 v2(12.83,72.52) ; U16.10 v2(43.68,33.02)
  TOP w0.305: U16.11 43.68,24.52 v2(43.94,24.26) 44.33,24.65 U16.12 ; U16.19 v2(48.88,24.39) ; U16.13 44.98,24.52 v2(45.24,24.26) 45.63,24.65 U16.14
  TOP w0.381: U2.E14 35.44,55.45 v1(35.04,55.05) ; v1(35.84,52.65) 35.44,52.25 U2.J14 ; U2.H7 v1(29.44,53.45) ; v1(35.04,53.45) 34.64,53.05 U2.H13 ; U3.D8 v1(23.31,73.25) ; v2(16.76,44.32) 16.95,44.14 D3.1 17.53,44.61 v2(17.53,45.47) ; v2(17.53,45.47) v2(16.76,45.47) ; v2(17.53,45.47) 18.54,45.47 C84.2 ; v1(34.55,21.94) 34.95,21.54 U11.E11 ; U3.P9 v1(32.11,74.05) ; U2.H11 v1(33.44,53.45) ; v1(40.64,59.05) 40.24,58.65 U2.A20 ; U2.T14 v1(35.84,46.25) ; v1(25.44,49.45) 25.84,49.85 U2.M2 ; U2.L11 v1(33.44,50.25) ; Y1.4 38.91,34.8 v2(39.5,34.8) ; U2.N8 30.64,49.05 v1(30.24,48.65) ; U2.K13 34.64,51.45 v1(35.04,51.85) ; U2.U7 29.84,45.85 v1(30.24,45.45) ; 28.83,36.7 v2(28.83,35.56) ; U2.M4 27.44,49.85 v1(27.04,50.25) ; v1(26.24,45.45) 26.64,45.85 U2.U3 ; U2.A1 v1(25.44,58.25) ; U2.W12 v1(33.44,44.65) U2.V11 ; U11.L9 v1(33.75,16.34) ; U3.J2 v1(28.11,68.45) ; v1(35.04,45.45) 34.64,45.85 U2.U13 ; U2.B11 v1(33.44,58.25) ; U3.T9 v1(33.71,74.05) ; U2.L12 33.84,50.65 v1(34.24,50.25) ; U11.C3 v1(28.15,23.54) ; U2.M12 v1(34.24,49.45) ; v1(38.24,56.65) 37.84,56.25 U2.D17 ; 38.48,37.72 v2(38.48,36.83) ; U2.P7 29.84,48.25 v1(29.44,47.85) ; U2.J18 38.64,52.25 v1(39.04,52.65) 39.44,53.05 U2.H19 ; U11.H5 v1(29.75,18.74) ; v2(4.19,29.34) 4.19,28.3 CN1.9 3.17,28.43 v2(3.17,29.34) ; v1(35.04,46.25) 34.64,46.65 U2.T13 ; v2(11.18,35.31) 10.82,35.31 SW1.3 ; v2(16,37.47) 16,36.32 16.64,35.69 v2(17.27,35.69) C63.2 ; R77.1 v2(36.45,30.86) ; U2.J12 33.84,52.25 v1(34.24,52.65) ; SW1.4 v2(9.27,30.56) ; U3.M9 v1(29.71,74.05) ; U2.N10 32.24,49.05 v1(31.84,48.65) ; U17.2 42.04,9.53 v2(42.29,9.27) ; D2.1 v2(20.13,35.5) ; U2.E19 39.44,55.45 v1(39.84,55.85) ; v1(31.04,47.85) 31.44,48.25 U2.P9 ; U2.P13 v1(35.04,47.85) ; v2(3.26,15.49) 3.26,14.6 CN1.10 4.27,14.63 v2(4.27,15.49) ; v1(33.44,51.85) 33.04,51.45 U2.K11 ; U2.M10 32.24,49.85 v1(31.84,49.45) ; v1(29.44,49.45) 29.84,49.85 U2.M7 ; U2.F2 25.84,54.65 v1(26.24,55.05) ; R90.2 v2(23.24,35.56) ; U11.A1 v1(26.55,25.14) ; 30.73,36.7 v2(30.73,35.56) ; U2.V4 27.44,45.05 v1(27.04,44.65) ; U11.F10 v1(33.75,21.14) ; U2.Y9 31.44,43.45 v1(31.04,43.05) ; U8.2 v2(21.21,25.15) ; SW2.4 v2(50.38,14.14) ; U11.G9 v1(33.75,20.34) U11.G10 ; v2(17.74,58.04) C45.2 ; 37.34,37.72 v2(37.34,36.83) ; C79.2 v2(17.08,63.69) ; U2.C2 v1(25.44,57.45) ; v1(31.84,50.25) 32.24,50.65 U2.L10 ; U2.Y20 40.24,43.45 v1(40.64,43.05) ; U2.U11 v1(33.44,45.45) ; v2(12.57,15.49) 12.57,14.63 CN1.12 11.56,14.6 v2(11.56,15.49) ; v1(24.11,73.25) 24.5,73.65 U3.E8 ; v1(25.44,44.65) 25.84,45.05 U2.V2 ; U2.P19 39.44,48.25 v1(39.84,48.65) ; R12.2 v2(17.02,61.21) ; U11.H12 v1(36.15,18.74) ; U3.F9 v1(25.71,74.05) ; v2(42.04,61.34) 40.77,62.61 C38.2 ; U2.T3 26.64,46.65 v1(26.24,46.25) ; C2.2 v2(51.05,66.67) ; U11.N13 v1(36.15,14.74) ; U2.R18 38.64,47.45 v1(39.04,47.05) ; U3.E1 24.5,68.05 v1(24.11,67.65) U3.D1 ; U2.R5 28.24,47.45 v1(27.84,47.85) ; U2.U19 v1(39.84,46.25) ; U5.3 v2(51.93,60.7) ; U3.J8 v1(28.11,74.05) ; U2.P11 v1(33.44,47.85) ; v1(24.48,46.65) 24.51,46.65 25.04,46.65 U2.T1 ; U2.G12 33.84,53.85 v1(34.24,54.25) ; v1(28.64,44.65) 29.04,44.25 U2.W6 ; v1(31.04,50.25) 31.44,50.65 U2.L9 ; U2.U12 33.84,45.85 v1(34.24,45.45) ; U2.H9 v1(31.04,53.45) ; U2.M18 38.64,49.85 v1(39.04,49.45) ; 36.2,37.72 v2(36.2,36.83) ; U2.K12 33.84,51.45 v1(34.24,51.85) ; U2.N14 v1(35.84,48.65) ; SW2.3 v2(50.38,9.99) ; U11.A13 v1(36.95,25.14) ; v1(35.04,44.65) 34.64,45.05 U2.V13 ; U2.B16 v1(37.44,58.25) ; U2.M13 v1(35.04,49.45) ; D4.1 v2(16.95,40.96) 16.7,40.96 v2(16,40.26) ; U2.E8 v1(30.24,55.85) ; U3.T1 v1(32.9,68.45) ; D7.1 v2(45.12,9.44) ; U2.G14 35.44,53.85 v1(35.84,54.25) ; U11.J4 v1(28.95,17.94) ; 34.54,36.7 32.64,36.7 32.55,36.61 v2(32.55,35.56) ; U11.G5 v1(29.75,20.34) ; U2.L8 30.64,50.65 v1(30.24,50.25) ; U3.M1 v1(30.51,68.45) ; U2.B3 v1(26.24,57.45) ; U2.L19 v1(39.84,50.25) ; C5.2 v2(17.02,62.36) ; U2.G8 v1(30.24,54.25) ; U2.U14 v1(35.84,45.45) ; D5.1 15.62,34.42 v2(15.88,34.16) ; v2(4.45,22.48) 5.25,23.28 CN1.6 ; U18.2 v2(15.75,32.26) ; U11.N1 v1(26.55,15.54) ; v1(24.64,43.05) 25.04,43.45 U2.Y1 ; U2.G10 v1(31.84,54.25) ; U11.F3 v1(28.15,21.14) ; U3.E2 v1(24.11,68.45) ; v1(28.64,57.45) 28.24,57.85 U2.B5 ; U11.M6 v1(30.55,15.54) ; v1(35.04,58.25) 34.64,57.85 U2.B13 ; v1(31.04,51.85) 31.44,51.45 U2.K9 ; U2.J10 v1(31.84,52.65) ; U3.P1 v1(31.3,67.65) ; C75.2 v2(44.83,36.32) ; U11.B8 v1(32.95,24.34) ; v2(11.47,29.34) 11.47,28.43 CN1.11 12.49,28.3 v2(12.49,29.34) ; U3.G9 v1(26.51,74.05) U3.G8 ; U2.J9 v1(31.04,52.65) ; U2.L14 v1(35.84,50.25) ; U2.U10 32.24,45.85 v1(31.84,45.45) U2.V10 ; U2.N12 v1(34.24,48.65) ; U2.R2 v1(25.44,47.85) ; U2.J8 v1(30.24,52.65) ; v1(38.24,54.25) 37.84,53.85 U2.G17 ; C94.2 v2(46.86,12.45) ; U11.D2 v1(28.15,21.94) ; U2.H4 27.44,53.05 v1(27.04,53.45) ; U4.F7 v1(43.89,72.26) ; U7.2 v2(18.8,18.16) ; v1(42.29,74.66) 41.89,75.06 U4.C5 ; U3.A9 v1(21.71,74.05) U3.B9 ; U2.B19 39.44,57.85 v1(39.84,58.25) ; U3.B3 v1(22.51,69.25) ; v1(38.24,44.65) 37.84,45.05 U2.V17 ; U11.N3 v1(28.15,14.74) ; U11.H4 v1(28.95,18.74) ; U2.E11 v1(33.44,55.85) ; U11.F13 v1(36.95,21.14) ; U2.M9 31.44,49.85 v1(31.04,49.45) ; U2.K10 v1(31.84,51.85) ; v2(35.18,33.02) 35.48,33.32 Y1.2 v2(36.49,31.75) ; U5.4 v2(51.91,61.95) ; C37.2 v2(12.83,32.26) ; U3.G1 v1(26.51,68.45) ; U2.J2 v1(25.44,52.65) ; U11.G7 v1(31.35,20.34) ; R76.1 v2(37.72,30.86) ; U5.5 v2(47.41,61.95) ; 45.85,19.43 v2(45.85,20.45) ; R67.2 v2(23.88,13.46) ; U2.M11 v1(33.44,49.45) ; U2.J11 v1(33.44,52.65) ; U2.K7 v1(29.44,51.85) ; U3.B1 22.34,67.81 ; U4.K8 v1(44.69,69.06) ; U11.E13 v1(36.15,21.94) ; U11.E2 v1(27.35,21.94) ; U4.K3 v1(39.89,69.86) ; U11.D5 v1(29.75,22.74) ; U10.2 v2(9.14,42.16) ; U2.E5 v1(27.84,55.85) ; X1.2 v2(44.28,21.3) ; U2.B8 v1(30.24,58.25)
  TOP w0.508: 5.31,38.66 J5.4 ; J5.4 7.19,38.66 ; J5.4 6.25,39.6 ; J5.4 6.25,37.72 ; J6.10 57.66,23.42 ; J6.10 56.59,22.35 ; J6.10 57.66,21.28 ; J6.10 58.73,22.35 ; v2(9.78,58.42) 10.85,58.42 C89.2 10.99,57.15 v2(9.78,57.15) ; J1.11 22,89.02 ; 17,0.98 J2.8 ; J2.13 23,5.02 ; 50.02,2 J2.40 49,0.98 ; J5.S2 3.54,37.3 ; J5.S2 1.84,35.59 ; J5.S2 5.25,35.59 ; J5.S2 3.54,33.89 ; 1.35,52.58 2.41,52.58 ; 2.41,52.58 2.41,53.65 ; 2.41,52.58 2.41,51.51 ; 2.41,52.58 3.48,52.58 ; 2.41,54.05 2.41,55.12 ; 2.41,55.12 3.48,55.12 ; 2.41,55.12 2.41,56.19 ; 2.41,55.12 1.35,55.12 ; 56,81.69 H3.1 51.69,86 ; 2.41,56.59 2.41,57.66 ; 2.41,57.66 3.48,57.66 ; 2.41,57.66 1.35,57.66 ; 2.41,57.66 2.41,58.73 ; 43,0.98 J2.34 ; 10.98,88 J1.1 12,89.02 ; J6.2 58.73,32.51 ; J6.2 57.66,33.58 ; J6.2 57.66,31.44 ; J6.2 56.59,32.51 ; 1.35,72.9 J3.3 ; J3.3 2.41,71.83 ; J3.3 3.48,72.9 ; J3.3 2.41,73.97 ; J1.7 18,89.02 ; 3.54,47.03 J5.S1 ; J5.S1 1.84,48.73 ; J5.S1 5.25,48.73 ; J5.S1 3.54,50.44 ; 2.41,69.29 J3.5 ; J3.5 2.41,71.43 ; J3.5 1.35,70.36 ; J3.5 3.48,70.36 ; 8.31,86 H4.1 4,81.69 ; C86.2 v2(16.64,48.01) ; 4,8.31 H1.1 8.31,4 ; 47,0.98 J2.38 ; 26,84.98 J1.16 ; 36,84.98 J1.26 ; R83.1 v2(47.5,21.59) ; C110.2 v2(49.66,21.59) ; J1.5 16,89.02 ; J1.3 14,89.02 ; 51.69,4 H2.1 56,8.31 ; C47.2 v2(17.02,59.56) ; J1.21 32,89.02 ; J2.3 13,5.02 ; 45,0.98 J2.36
  BOTTOM w0.305: U15.11 8.5,62.67 v2(8.83,62.99) 9.15,62.67 U15.12 ; U15.13 9.8,62.67 v2(10.13,62.99) 10.45,62.67 U15.14 ; U15.16 11.76,62.67 v2(11.43,62.99) 11.1,62.67 U15.15 ; U15.10 v2(8.5,54.49)
  BOTTOM w0.381: v2(38.48,36.83) 38.61,36.96 38.61,37.72 ; C88.1 v2(4.95,21.08) ; C64.2 40.64,43.05 v1(40.64,43.05) ; C11.2 v2(26.29,77.09) ; v1(27.84,47.85) 27.84,47.22 28.07,46.99 C53.2 ; C39.2 29.44,51.54 v1(29.44,51.85) 28.97,52.32 C40.2 ; 25.44,50.71 22.63,50.71 C48.2 ; 25.44,50.71 C42.2 ; 25.44,50.71 v1(25.44,49.45) ; C27.2 44.83,72.64 44.45,72.26 v1(43.89,72.26) ; C72.2 38.24,56.88 v1(38.24,56.65) ; C67.2 v2(35.43,41.91) ; C24.2 30.13,68.07 v1(30.51,68.45) ; C4.2 17.65,60.2 v2(17.02,59.56) ; v1(33.44,51.85) 33.44,51.4 C50.2 ; C108.2 30.98,15.11 v1(30.55,15.54) ; C14.2 v2(24.38,77.09) ; v2(16.26,72.9) 16.64,72.9 16.89,72.64 R89.2 ; v2(12.83,73.53) 13.08,73.28 C114.2 ; C103.2 27.94,23.75 v1(28.15,23.54) ; C104.2 34.04,15.24 33.75,15.53 v1(33.75,16.34) ; R74.1 32.8,30.14 v2(32.8,30.86) ; v1(26.51,74.05) 27.15,73.41 C20.2 ; C57.2 31.5,51.4 v1(31.04,51.85) ; C56.2 32.06,52.07 v1(31.84,51.85) ; v1(21.71,70.1) 21.71,70.09 C13.2 ; v1(22.51,69.25) 22.51,70.89 23.24,71.63 C22.2 ; C52.2 36.02,52.83 v1(35.84,52.65) ; C70.2 v2(40.26,78.87) ; R93.2 v2(27.05,36.2) ; C85.2 R36.2 16.89,48.26 v2(16.64,48.01) ; v1(30.24,55.85) 29.72,55.33 C44.2 ; R78.1 30.1,28.96 30.99,28.07 v2(31.24,28.07) ; v2(32.64,65.66) 32.51,65.53 C21.2 C19.2 ; v1(39.84,46.25) 40.13,45.96 C68.2 ; v2(42.04,67.56) 42.29,67.82 C26.2 ; R13.2 v2(29.59,77.09) ; C69.2 C65.2 ; C65.2 40.77,65.79 41.27,66.29 v2(42.04,66.29) v2(42.04,65.41) C76.2 C65.2 ; C46.2 33.14,44.96 v1(33.44,44.65) ; C43.2 31.84,54.95 v1(31.84,54.25) 32.66,54.25 C59.2 ; 40.89,37.72 v2(40.89,36.83) ; C66.2 40.26,59.44 v1(40.64,59.05) ; v1(35.84,50.25) 36.13,50.55 C51.2 ; U9.1 13.72,38.48 14.22,37.97 14.22,37.21 v2(13.34,36.32) C90.2 ; v1(36.95,21.14) 36.45,20.64 36.45,20.45 ; v2(36.2,36.83) 35.56,36.83 35.18,37.21 R30.2 ; C49.2 36.18,48.65 v1(35.84,48.65) ; R6.2 v2(13.59,52.2) ; R63.1 v2(11.18,35.31) ; v1(29.44,47.85) 29.44,47.52 29.84,47.12 ; C99.2 31.62,20.07 v1(31.35,20.34) ; C16.2 22.23,74.57 v1(21.71,74.05) ; 36.7,56.01 36.7,55.12 C54.2 36.32,54.99 36.07,55.24 35.23,55.24 v1(35.04,55.05) ; C9.2 v2(27.18,77.09) ; C8.2 22.48,67.62 v1(22.51,67.65) ; C10.2 v2(33.02,77.09) ; v1(34.55,21.94) 33.94,21.94 C106.2 ; C32.2 R90.2 v2(23.24,35.56) ; C28.2 C25.2 42.29,74.66 v1(42.29,74.66) ; C7.2 v2(23.37,77.09) ; R92.2 v2(25.91,36.2) ; C100.2 29.75,19.02 v1(29.75,18.74) ; C23.2 v2(20.07,71.88) ; C29.2 C33.2 17.02,40.89 v2(16.95,40.96) ; v1(36.15,21.94) 36.45,22.24 36.45,22.73 ; R34.2 18.41,51.69 v2(17.27,50.55) ; v1(34.24,54.25) 34.24,55.32 C41.2 ; C36.2 v2(18.92,34.04) ; R14.2 v2(28.32,77.09) ; C15.2 C17.2 24.28,67.82 v1(24.11,67.65) ; C98.2 27.3,16.29 v1(26.55,15.54) ; v2(17.74,58.04) 18.8,59.09 R9.2 ; C6.2 v2(30.73,77.09) ; C87.2 v2(4.45,22.48) ; v2(17.53,45.47) 18.29,45.47 C34.2 ; C73.2 v2(41.27,78.87) ; v2(40.26,12.32) 42.16,12.32 ; v2(15.75,32.26) 16,32 R52.2 ; 36.45,19.43 36.45,19.04 v1(36.15,18.74) ; v1(36.15,14.74) 35.43,15.46 C107.2 ; C18.2 v2(25.4,77.09) ; C58.2 32.46,49.45 v1(31.84,49.45) ; C12.2 v2(34.04,77.09) ; R37.1 v2(24.51,39.37) ; v1(35.04,47.85) 35.31,47.59 C55.2 ; v1(28.15,21.94) 28.61,21.94 C96.2 ; C74.2 v2(39.24,78.87) ; R73.2 v2(42.29,9.27)
  BOTTOM w0.508: 6.25,37.72 J5.4 ; J5.4 6.25,39.6 ; J5.4 7.19,38.66 ; J5.4 5.31,38.66 ; 4,81.69 H4.1 8.31,86 ; J3.5 3.48,70.36 ; J3.5 1.35,70.36 ; J3.5 2.41,69.29 ; J3.5 2.41,71.43 ; 3.54,47.03 J5.S1 ; J5.S1 3.54,50.44 ; J5.S1 5.25,48.73 ; J5.S1 1.84,48.73 ; 56,8.31 H2.1 51.69,4 ; 14.99,64.9 v2(14.99,65.91) ; 17,0.98 J2.8 ; 2.41,55.12 3.48,55.12 ; 2.41,55.12 2.41,54.05 ; 2.41,55.12 1.35,55.12 ; 2.41,55.12 2.41,56.19 ; J6.10 57.66,23.42 ; J6.10 56.59,22.35 ; J6.10 58.73,22.35 ; J6.10 57.66,21.28 ; 26,84.98 J1.16 ; 2.41,56.59 2.41,57.66 ; 2.41,57.66 2.41,58.73 ; 2.41,57.66 3.48,57.66 ; 2.41,57.66 1.35,57.66 ; 43,0.98 J2.34 ; 45,0.98 J2.36 ; J5.S2 5.25,35.59 ; J5.S2 3.54,33.89 ; J5.S2 1.84,35.59 ; J5.S2 3.54,37.3 ; J6.2 57.66,33.58 ; J6.2 58.73,32.51 ; J6.2 56.59,32.51 ; J6.2 57.66,31.44 ; J1.5 16,89.02 ; 2.41,51.51 2.41,52.58 ; 2.41,52.58 1.35,52.58 ; 2.41,52.58 2.41,53.65 ; 2.41,52.58 3.48,52.58 ; J2.13 23,5.02 ; 12,89.02 J1.1 10.98,88 ; 2.41,71.83 J3.3 ; J3.3 3.48,72.9 ; J3.3 2.41,73.97 ; J3.3 1.35,72.9 ; J1.7 18,89.02 ; 8.31,4 H1.1 4,8.31 ; 37,0.98 J2.28 ; 49,0.98 J2.40 50.02,2 ; J2.23 33,5.02 ; J1.3 14,89.02 ; 47,0.98 J2.38 ; 27,0.98 J2.18 ; J2.3 13,5.02 ; J1.11 22,89.02
  vias: v2(1.27,80.64) v2(1.27,78.11) v2(1.65,24.51) v2(1.65,20.7) v2(1.65,16.89) v2(1.78,32.64) v2(1.78,28.83) v2(1.93,46.26) v2(1.93,42.45) v2(1.93,38.64) v2(2.54,12.32) v2(2.54,9.78) v2(5.08,80.64) v2(5.08,78.11) v2(5.59,32.64) v2(5.59,28.83) v2(6.35,14.86) v2(6.35,12.32) v2(6.35,9.78) v2(8.51,14.86) v2(8.64,66.67) v2(8.89,12.32) v2(8.89,9.78) v2(11.81,73.53) v2(14.22,6.1) v2(15.75,78.49) v2(16.13,84.2) v2(16.64,78.49) v2(16.89,77.34) v2(16.89,76.33) v2(16.89,14.73) v2(16.89,12.06) v2(16.89,9.53) v2(19.05,6.86) v2(19.43,14.73) v2(19.43,12.06) v2(19.43,9.53) v2(19.94,84.2) v2(21.72,17.02) v2(21.72,16) v2(23.88,26.8) v2(24.51,84.2) v2(24.89,26.8) v2(28.45,84.2) v2(29.34,12.7) v2(29.34,11.81) v2(33.4,7.37) v2(35.94,7.37) v2(42.29,7.37) v2(47.12,19.56) v2(47.12,17.02) v2(48.26,8.51) v2(48.26,5.97) v2(49.66,17.02) v2(50.8,8.51) v2(50.8,5.97) v2(52.2,30.73) v2(52.2,19.56) v2(52.2,17.02) v2(52.2,14.48) v2(52.2,11.94) v2(52.2,9.4) v2(52.58,25.91) v2(52.58,21.97) v2(54.74,19.56) v2(54.74,17.02) v2(54.74,14.48) v2(54.74,11.94) v2(54.74,9.4) v2(56.01,57.78) v2(56.01,56.9) v2(56.13,79.25) v2(57.28,19.56) v2(57.28,17.02) v2(58.29,72.9) v2(58.29,69.09) v2(58.29,65.28) v2(58.29,61.47) v2(58.29,57.66) v2(58.29,53.85) v2(58.29,50.04) v2(58.29,46.23) v2(58.29,42.42) v2(58.29,38.61) v2(58.29,34.8) v2(58.67,79.25)
